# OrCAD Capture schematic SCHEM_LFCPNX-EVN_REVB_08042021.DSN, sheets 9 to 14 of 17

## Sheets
9 Bank-6 Extended Bank: size B; title: Bank-6 Extened Bank
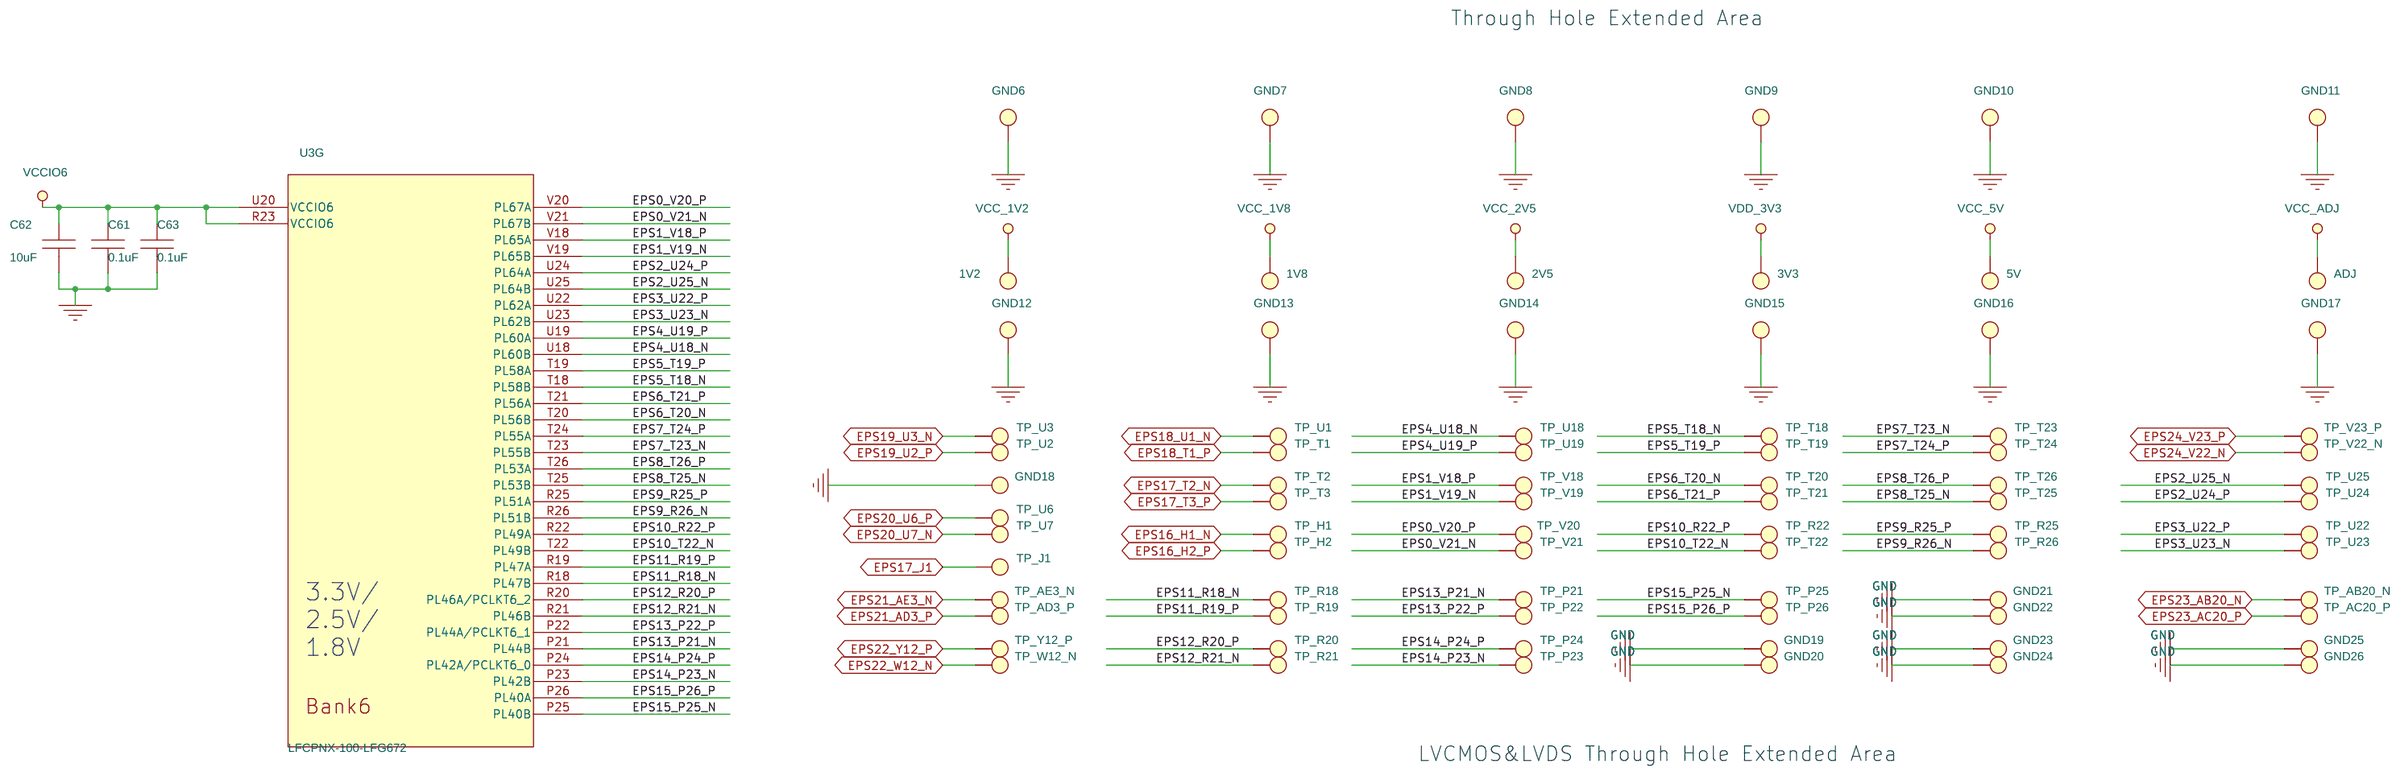
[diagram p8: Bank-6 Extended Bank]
10 Bank-7 Raspberry PI: size B; title: Bank-7 Raspberry PI
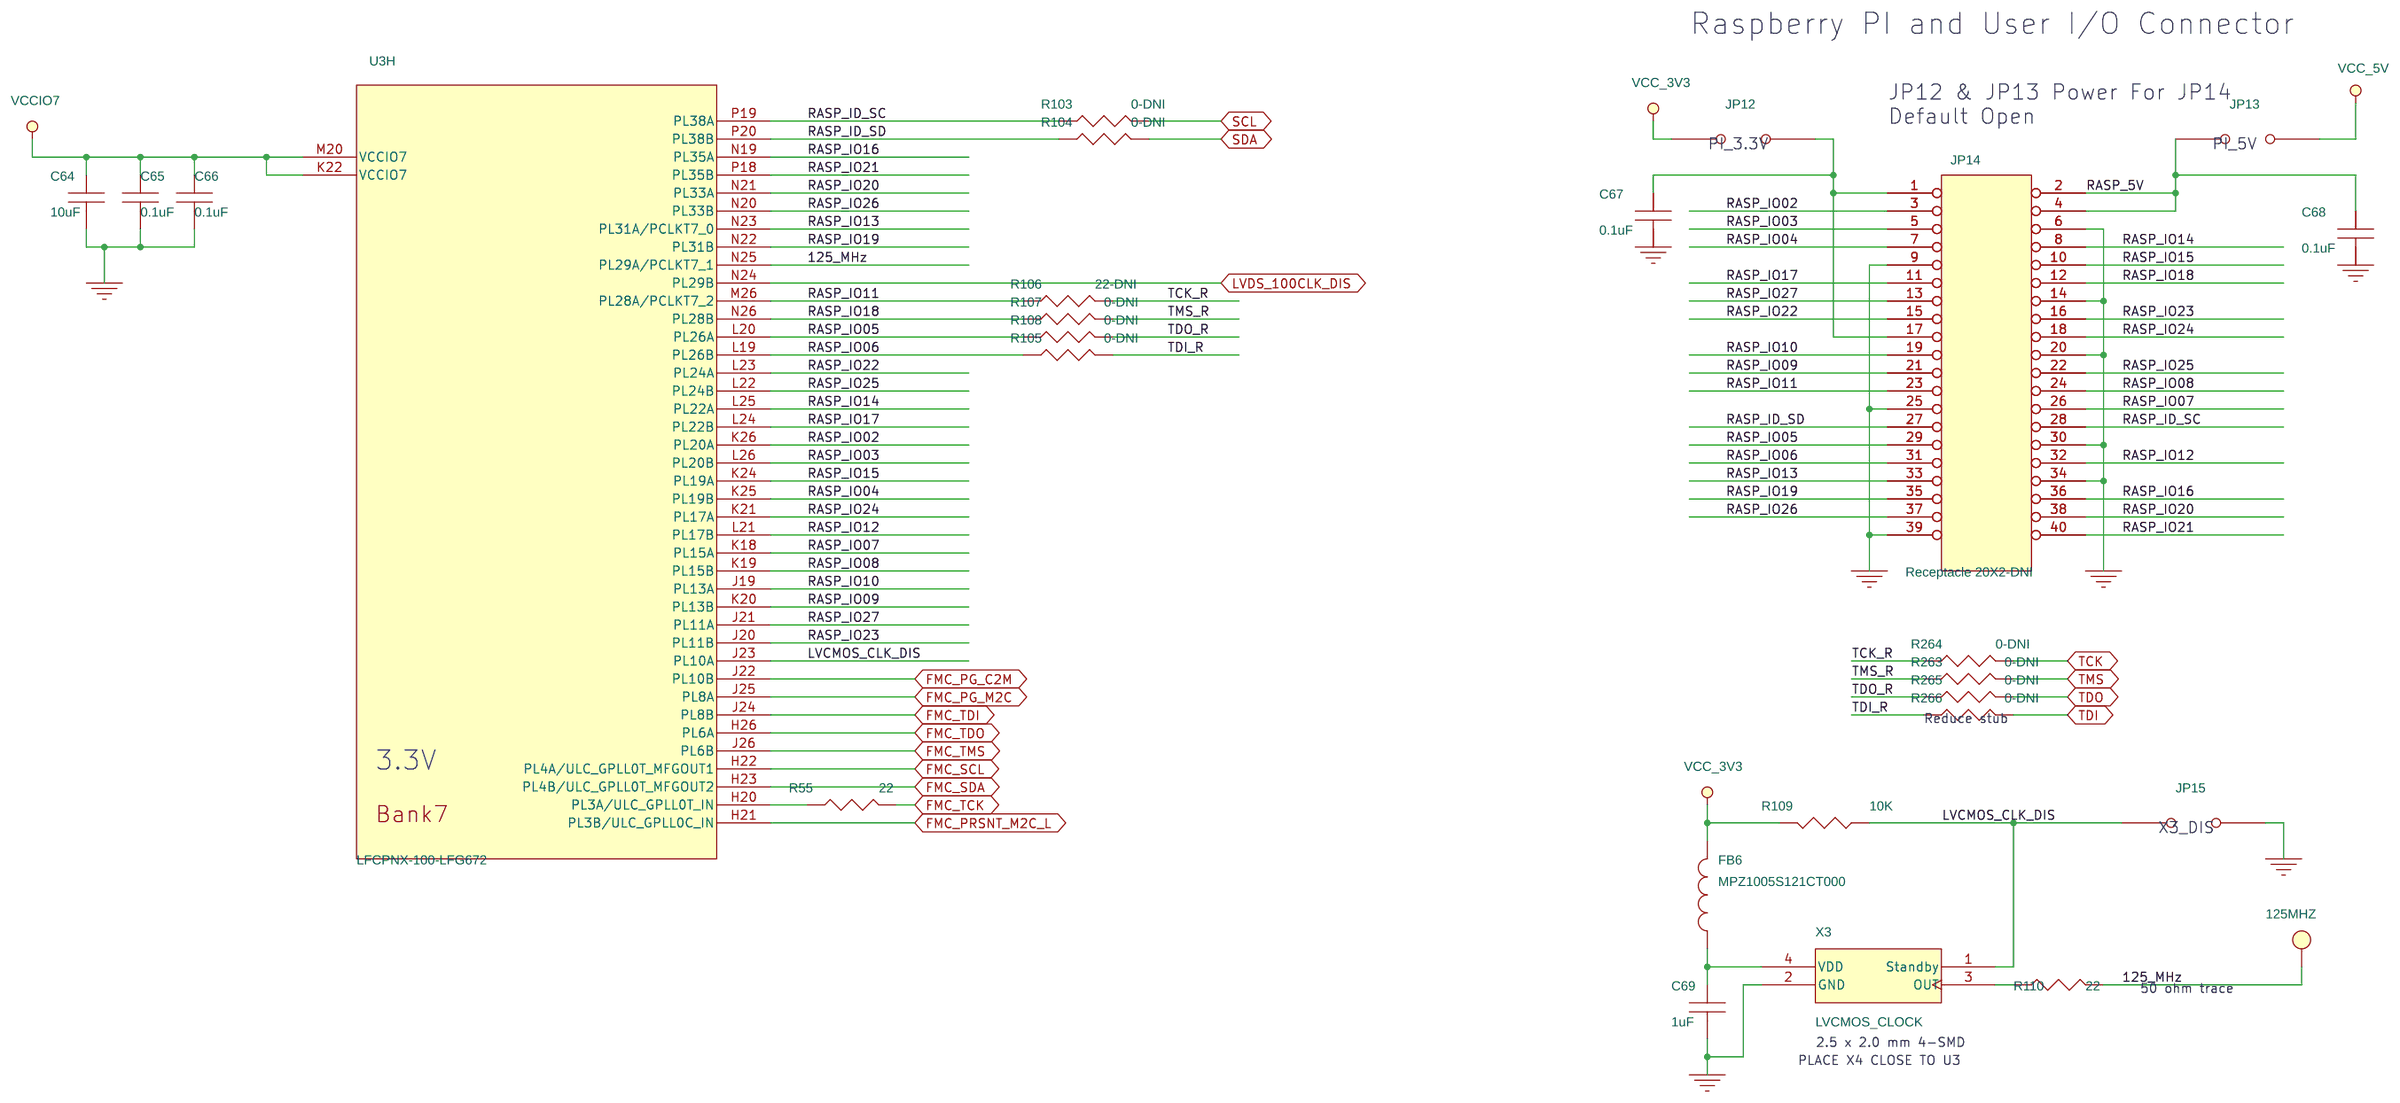
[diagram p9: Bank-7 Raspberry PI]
11 SerDes: size C; title: SerDes
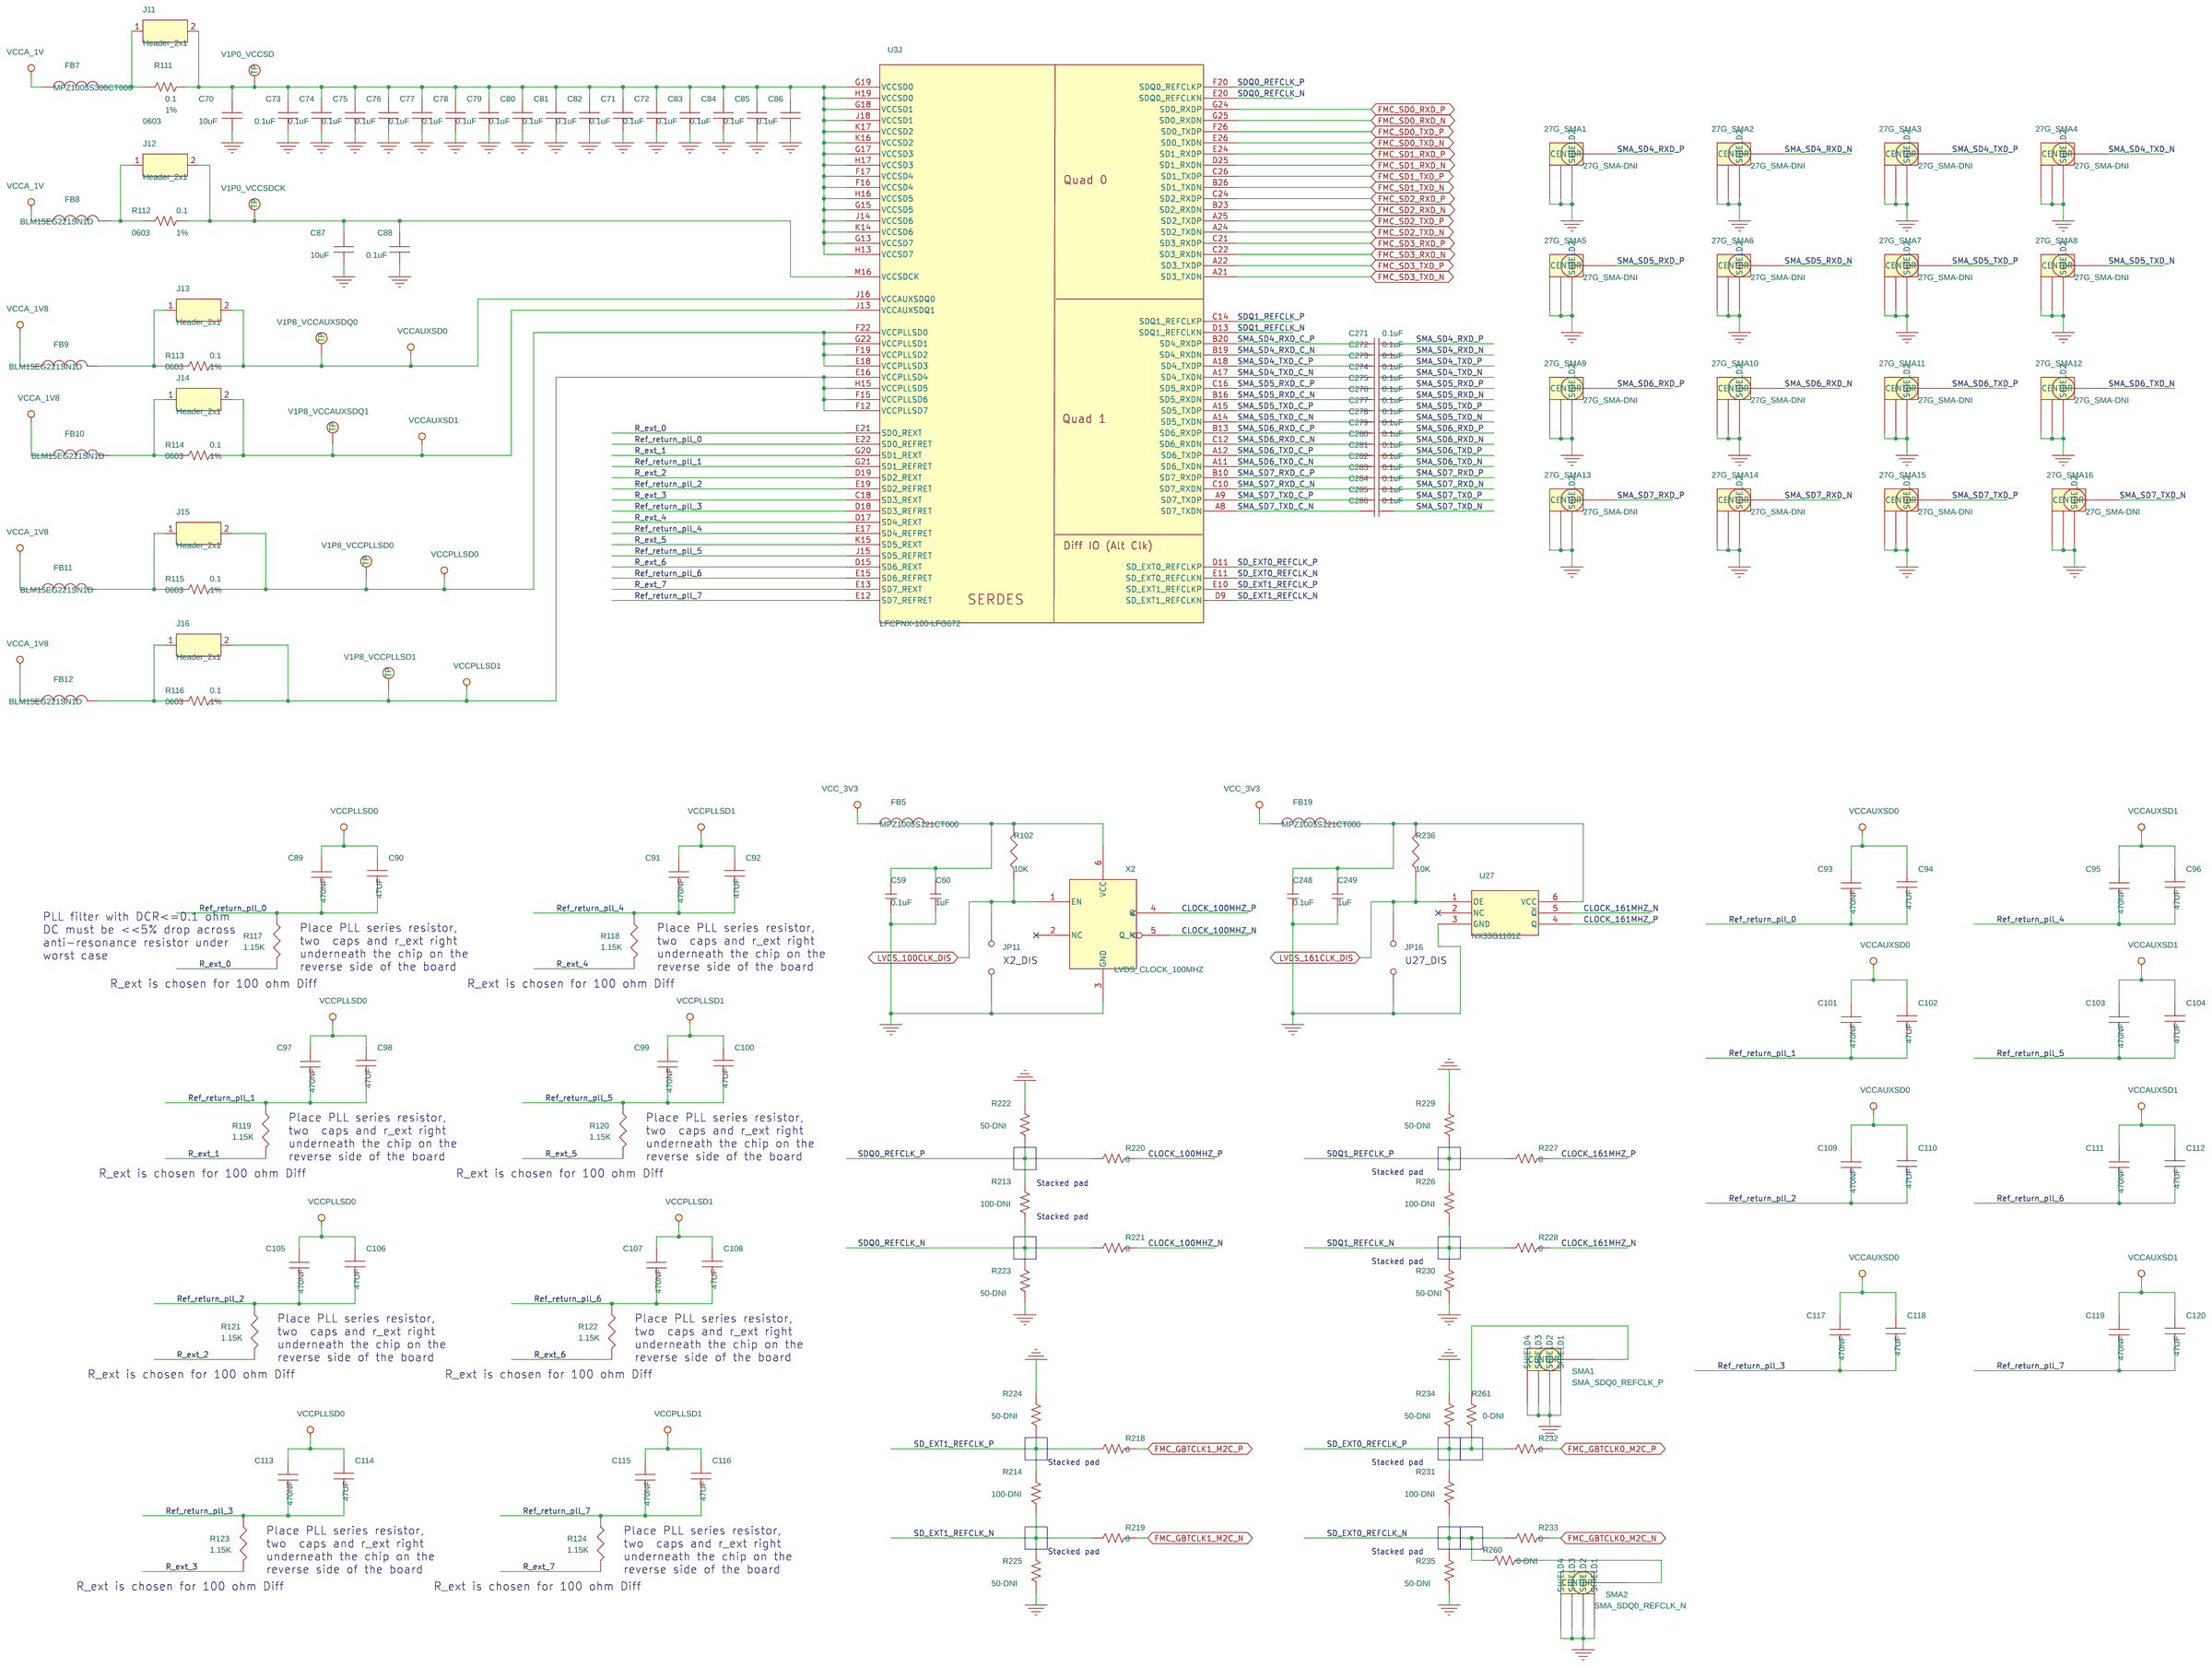
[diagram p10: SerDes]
12 ADC: size B; title: ADC
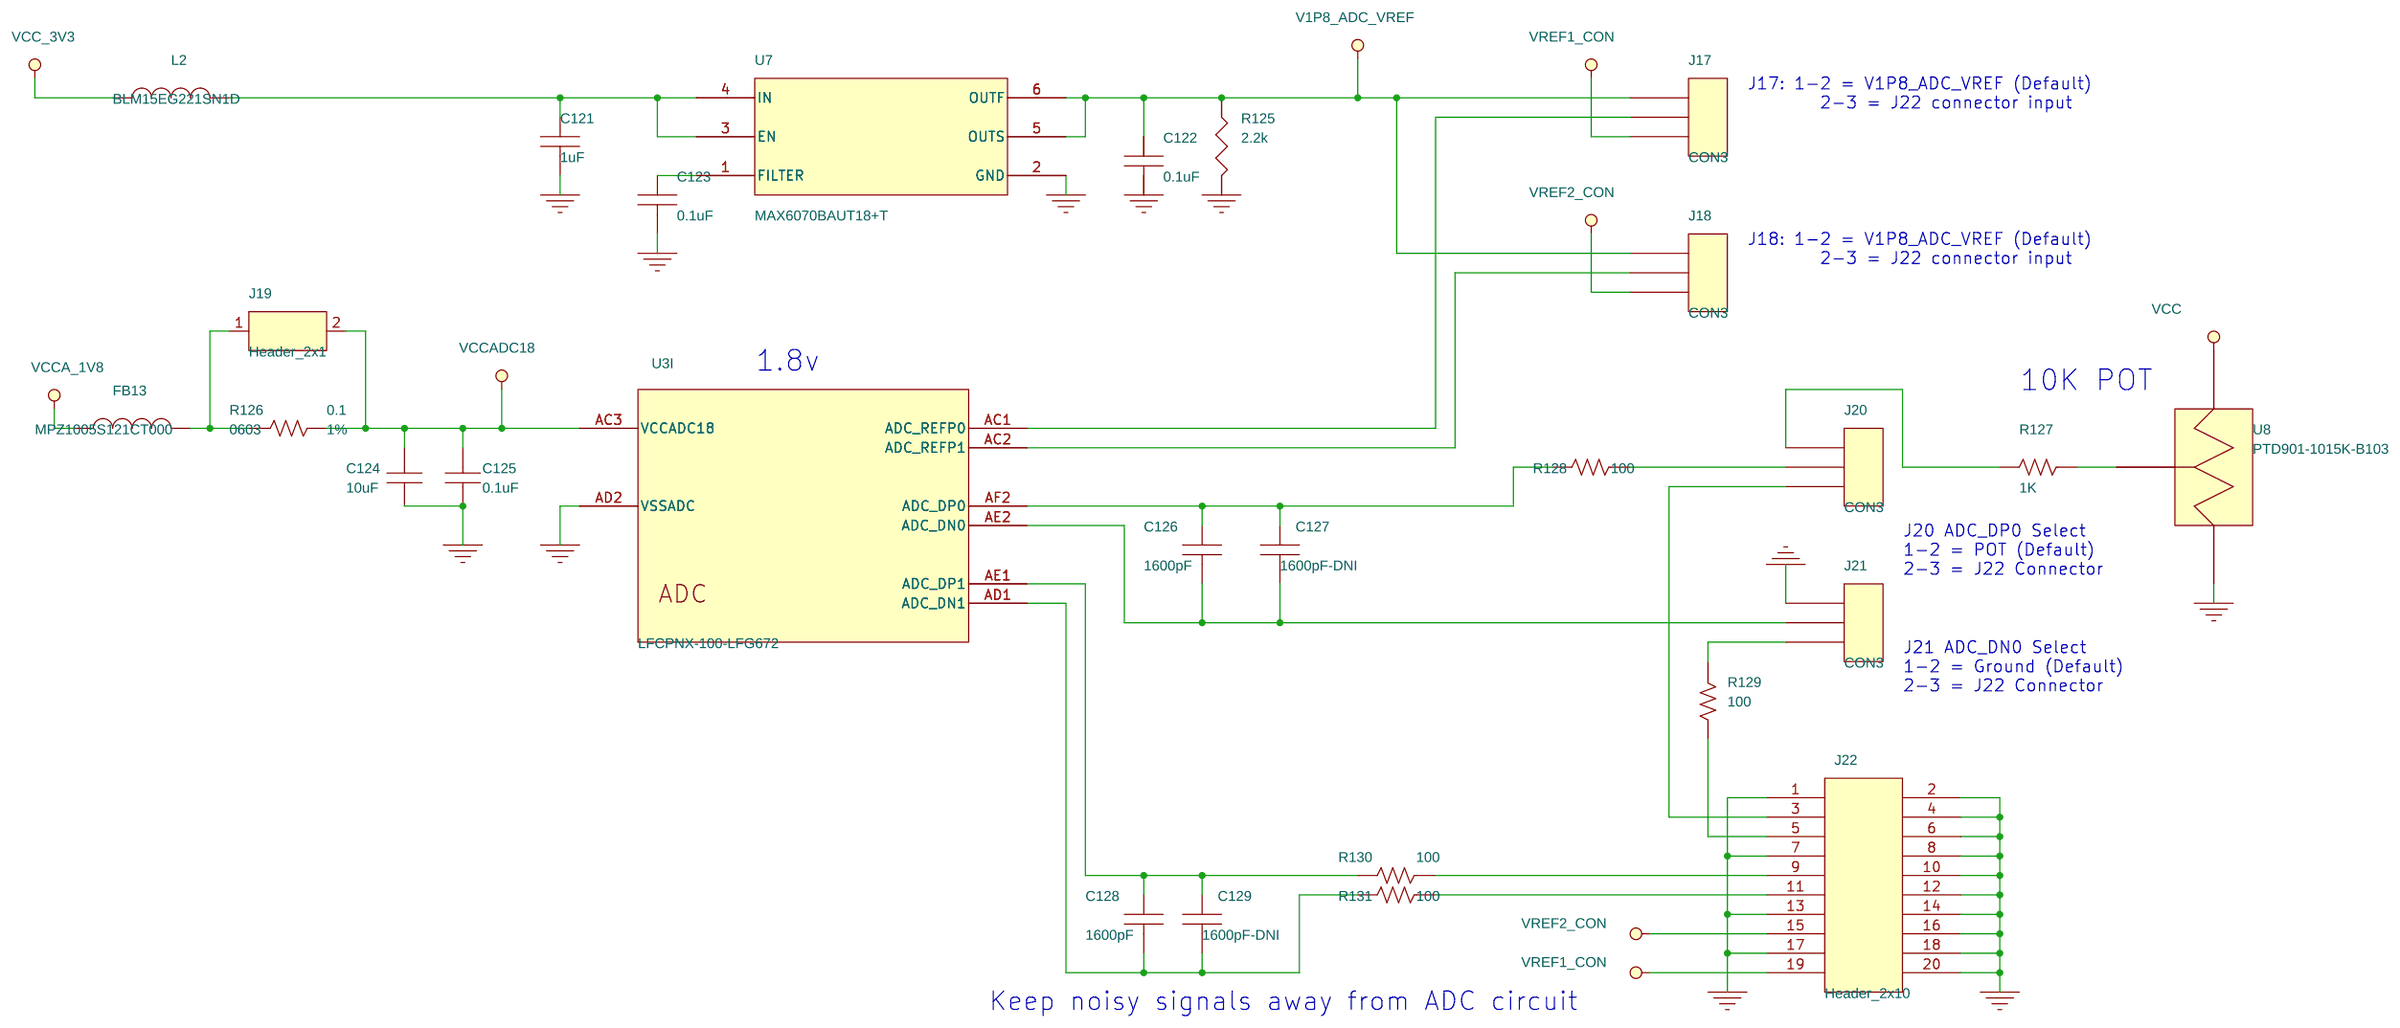
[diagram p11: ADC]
13 Bank Power: size B; title: Bank Power
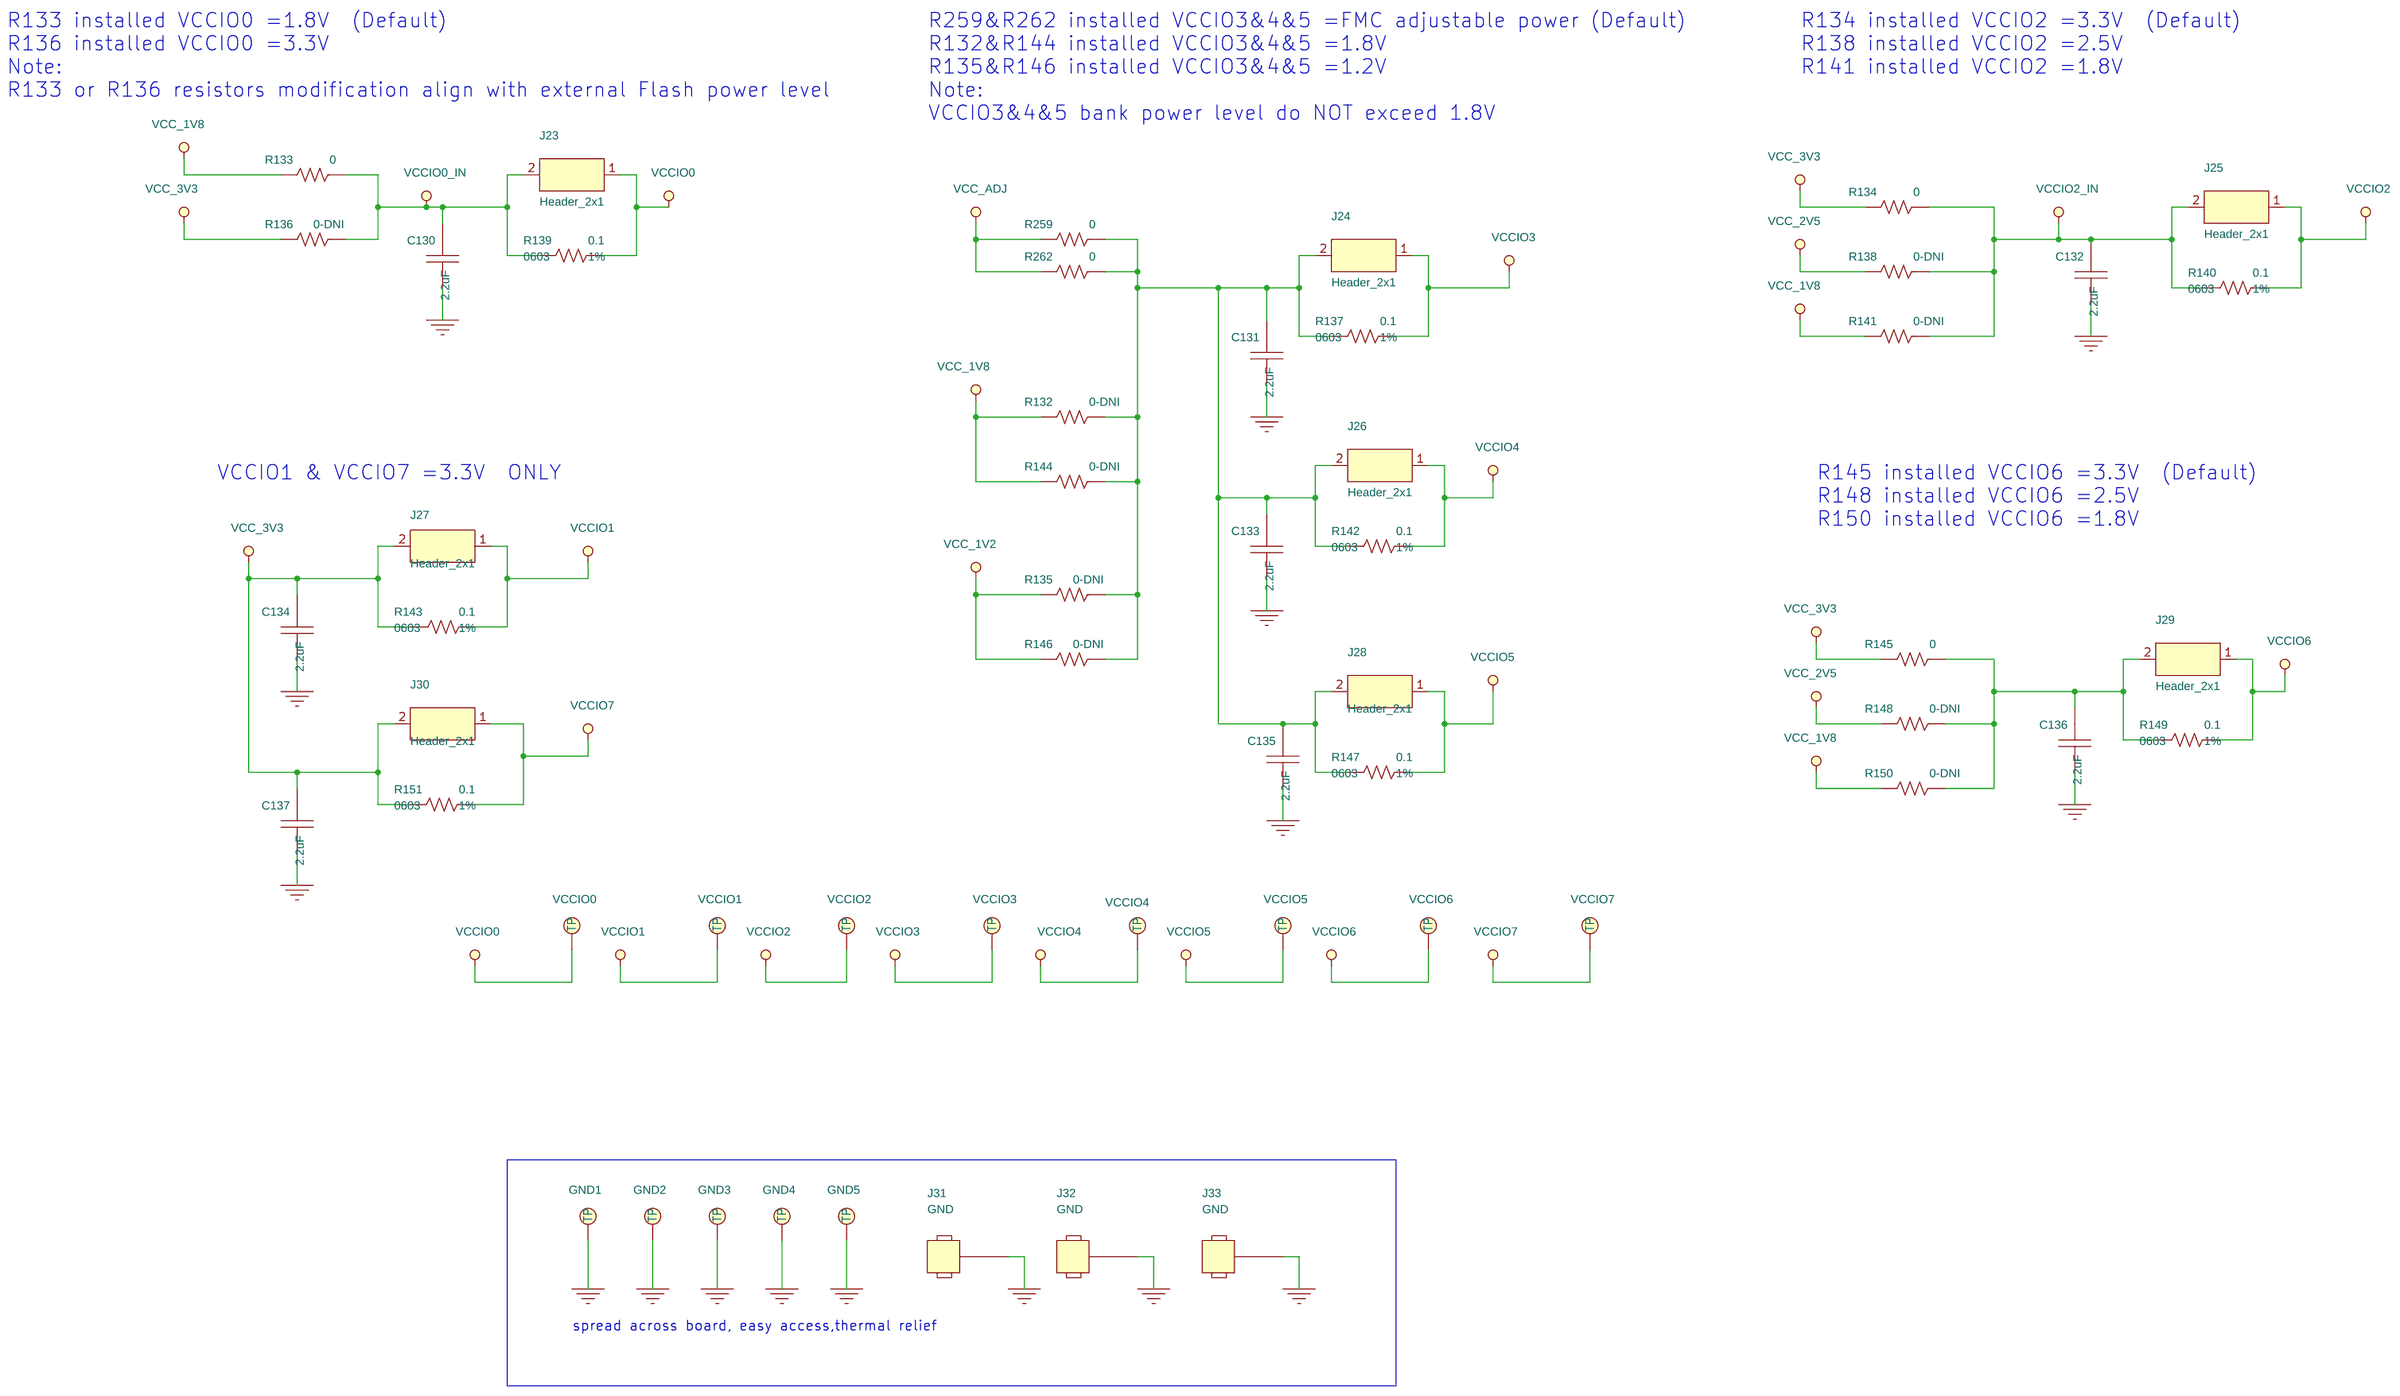
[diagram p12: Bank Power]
14 Power Decoupling: size B; title: Power Decoupling
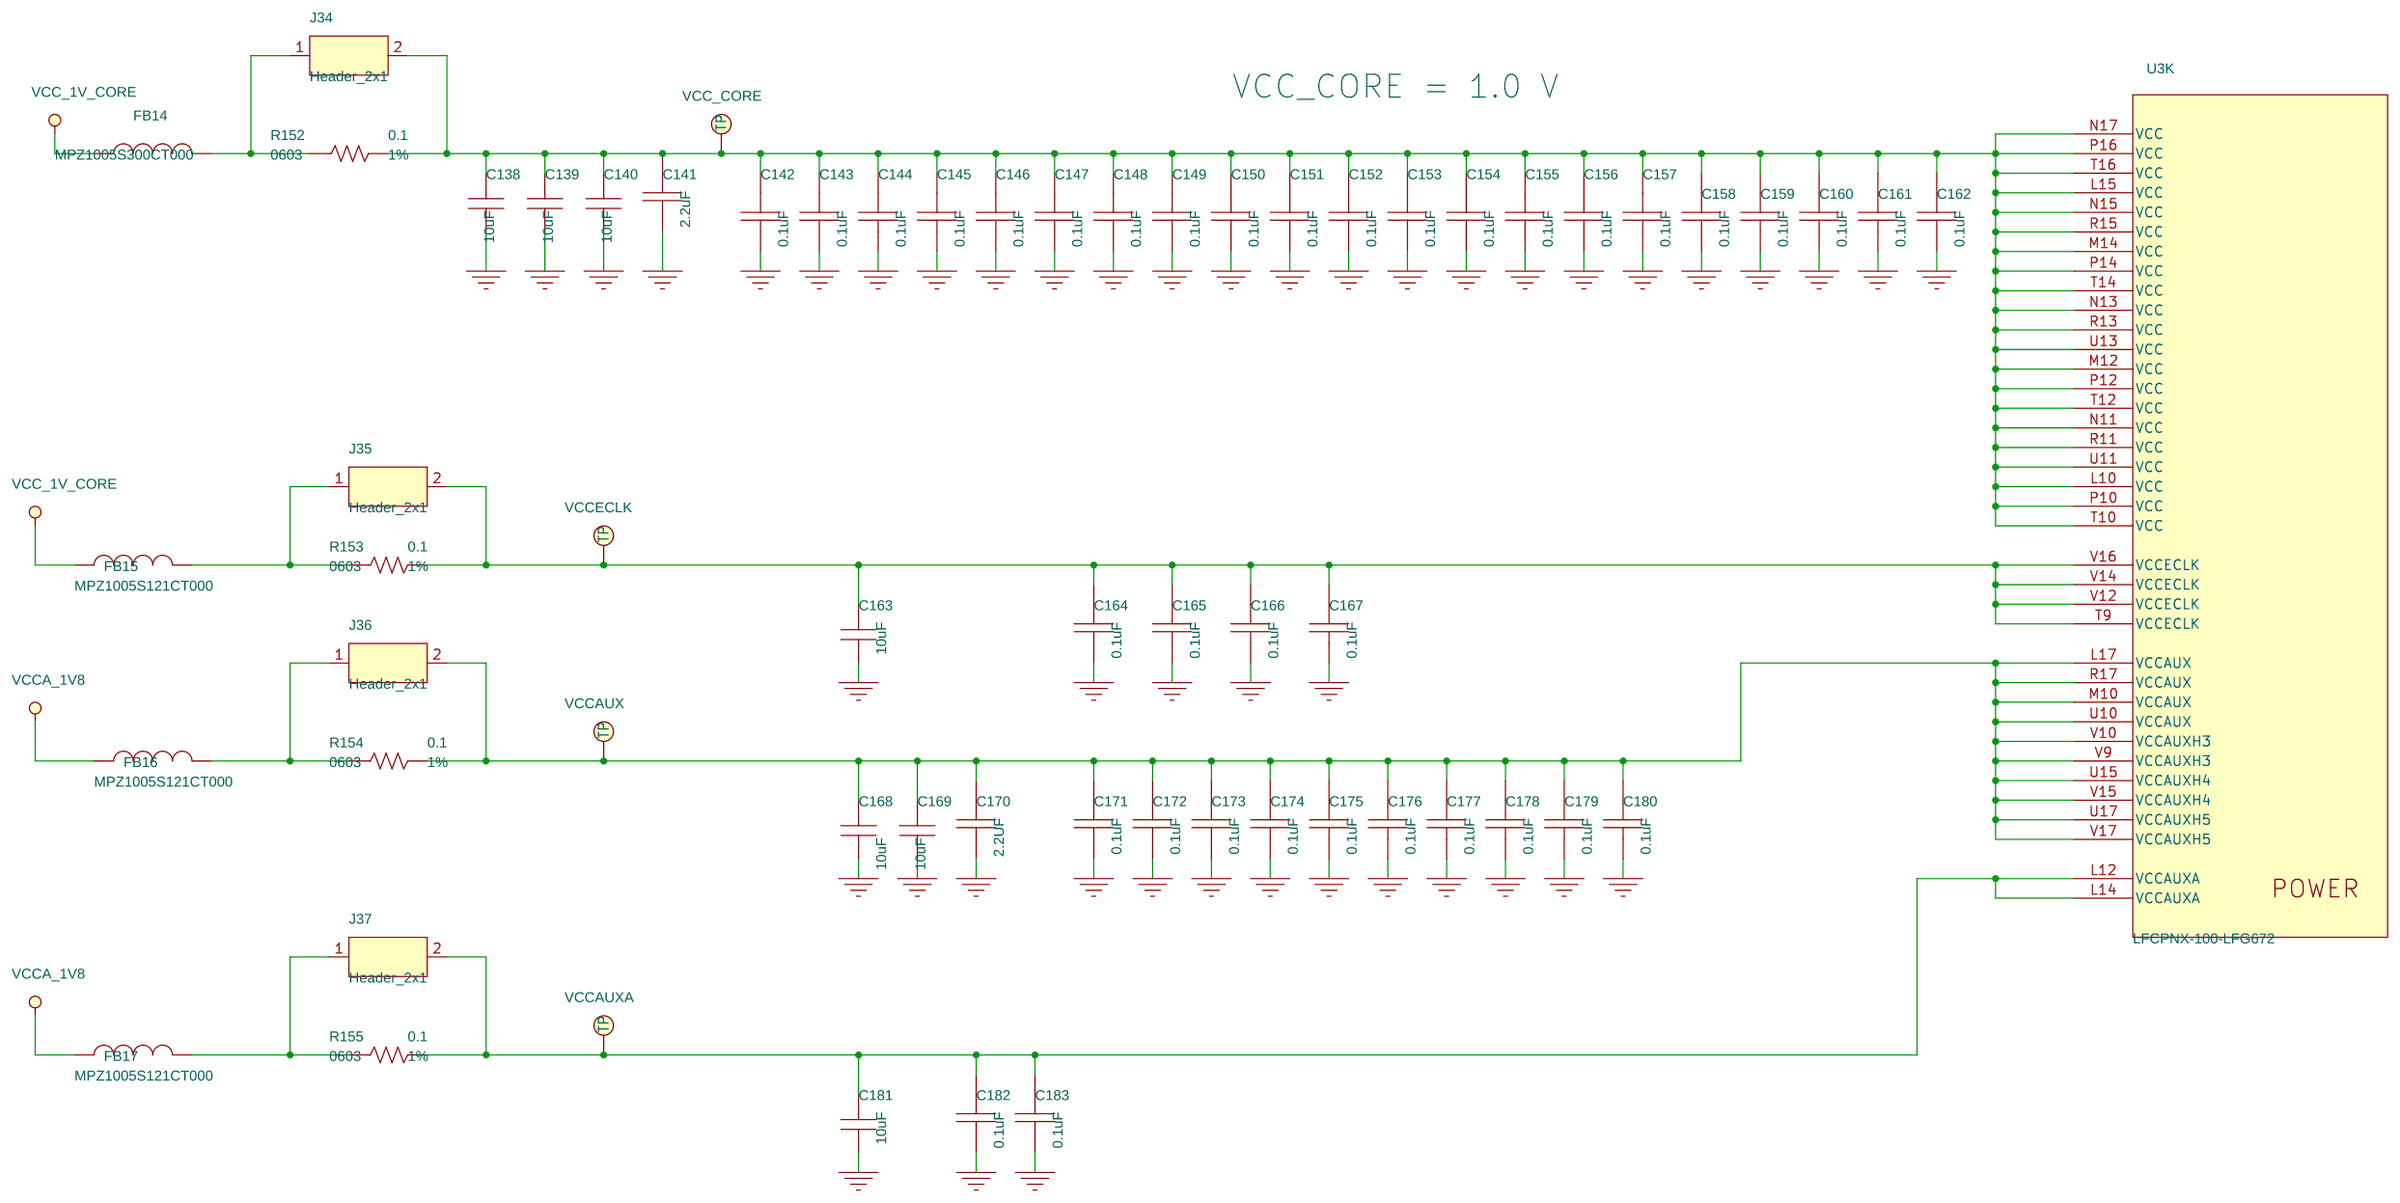
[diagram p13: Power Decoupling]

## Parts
sheet ADC
C121  1uF  [C0603]
C122  0.1uF  [C0201]
C123  0.1uF  [C0201]
C124  10uF  [C0402]
C125  0.1uF  [C0201]
C126  1600pF  [C0805]
C127  1600pF-DNI  [C0805]
C128  1600pF  [C0805]
C129  1600pF-DNI  [C0805]
FB13  MPZ1005S121CT000  [FB0402]
J17  CON3  [CON3]
J18  CON3  [CON3]
J19  Header_2x1  [Header_2x1]
J20  CON3  [CON3]
J21  CON3  [CON3]
J22  Header_2x10  [Header_2x10]
L2  BLM15EG221SN1D  [FB0402]
R125  2.2k  [R0603]
R126  0.1  [0603]
R127  1K  [R0805]
R128  100  [R0805]
R129  100  [R0805]
R130  100  [R0805]
R131  100  [R0805]
U7  MAX6070BAUT18+T  [SOT23-6_MAX6070]
U8  PTD901-1015K-B103  [PTD901_1015K_B103]
sheet Bank Power
C130  2.2uF  [RLP-133]
C131  2.2uF  [RLP-133]
C132  2.2uF  [RLP-133]
C133  2.2uF  [RLP-133]
C134  2.2uF  [RLP-133]
C135  2.2uF  [RLP-133]
C136  2.2uF  [RLP-133]
C137  2.2uF  [RLP-133]
GND1  TestPoint_Hole  [TP]
GND2  TestPoint_Hole  [TP]
GND3  TestPoint_Hole  [TP]
GND4  TestPoint_Hole  [TP]
GND5  TestPoint_Hole  [TP]
J23  Header_2x1  [Header_2x1]
J24  Header_2x1  [Header_2x1]
J25  Header_2x1  [Header_2x1]
J26  Header_2x1  [Header_2x1]
J27  Header_2x1  [Header_2x1]
J28  Header_2x1  [Header_2x1]
J29  Header_2x1  [Header_2x1]
J30  Header_2x1  [Header_2x1]
J31  GND  [TUR_TH]
J32  GND  [TUR_TH]
J33  GND  [TUR_TH]
R132  0-DNI  [R0603]
R133  0  [R0603]
R134  0  [R0603]
R135  0-DNI  [R0603]
R136  0-DNI  [R0603]
R137  0.1  [0603]
R138  0-DNI  [R0603]
R139  0.1  [0603]
R140  0.1  [0603]
R141  0-DNI  [R0603]
R142  0.1  [0603]
R143  0.1  [0603]
R144  0-DNI  [R0603]
R145  0  [R0603]
R146  0-DNI  [R0603]
R147  0.1  [0603]
R148  0-DNI  [R0603]
R149  0.1  [0603]
R150  0-DNI  [R0603]
R151  0.1  [0603]
R259  0  [R0603]
R262  0  [R0603]
VCCIO0  TP_S_40_63  [tp_s_40_63]
VCCIO1  TP_S_40_63  [tp_s_40_63]
VCCIO2  TP_S_40_63  [tp_s_40_63]
VCCIO3  TP_S_40_63  [tp_s_40_63]
VCCIO4  TP_S_40_63  [tp_s_40_63]
VCCIO5  TP_S_40_63  [tp_s_40_63]
VCCIO6  TP_S_40_63  [tp_s_40_63]
VCCIO7  TP_S_40_63  [tp_s_40_63]
sheet Bank-6 Extended Bank
1V2  T POINT R  [TP]
1V8  T POINT R  [TP]
2V5  T POINT R  [TP]
3V3  T POINT R  [TP]
5V  T POINT R  [TP]
ADJ  T POINT R  [TP]
C61  0.1uF  [C0201]
C62  10uF  [C0402]
C63  0.1uF  [C0201]
GND6  T POINT R  [TP]
GND7  T POINT R  [TP]
GND8  T POINT R  [TP]
GND9  T POINT R  [TP]
GND10  T POINT R  [TP]
GND11  T POINT R  [TP]
GND12  T POINT R  [TP]
GND13  T POINT R  [TP]
GND14  T POINT R  [TP]
GND15  T POINT R  [TP]
GND16  T POINT R  [TP]
GND17  T POINT R  [TP]
GND18  T POINT R  [TP]
GND19  T POINT R  [TP]
GND20  T POINT R  [TP]
GND21  T POINT R  [TP]
GND22  T POINT R  [TP]
GND23  T POINT R  [TP]
GND24  T POINT R  [TP]
GND25  T POINT R  [TP]
GND26  T POINT R  [TP]
TP_AB20_N  T POINT R  [TP]
TP_AC20_P  T POINT R  [TP]
TP_AD3_P  T POINT R  [TP]
TP_AE3_N  T POINT R  [TP]
TP_H1  T POINT R  [TP]
TP_H2  T POINT R  [TP]
TP_J1  T POINT R  [TP]
TP_P21  T POINT R  [TP]
TP_P22  T POINT R  [TP]
TP_P23  T POINT R  [TP]
TP_P24  T POINT R  [TP]
TP_P25  T POINT R  [TP]
TP_P26  T POINT R  [TP]
TP_R18  T POINT R  [TP]
TP_R19  T POINT R  [TP]
TP_R20  T POINT R  [TP]
TP_R21  T POINT R  [TP]
TP_R22  T POINT R  [TP]
TP_R25  T POINT R  [TP]
TP_R26  T POINT R  [TP]
TP_T1  T POINT R  [TP]
TP_T2  T POINT R  [TP]
TP_T3  T POINT R  [TP]
TP_T18  T POINT R  [TP]
TP_T19  T POINT R  [TP]
TP_T20  T POINT R  [TP]
TP_T21  T POINT R  [TP]
TP_T22  T POINT R  [TP]
TP_T23  T POINT R  [TP]
TP_T24  T POINT R  [TP]
TP_T25  T POINT R  [TP]
TP_T26  T POINT R  [TP]
TP_U1  T POINT R  [TP]
TP_U2  T POINT R  [TP]
TP_U3  T POINT R  [TP]
TP_U6  T POINT R  [TP]
TP_U7  T POINT R  [TP]
TP_U18  T POINT R  [TP]
TP_U19  T POINT R  [TP]
TP_U22  T POINT R  [TP]
TP_U23  T POINT R  [TP]
TP_U24  T POINT R  [TP]
TP_U25  T POINT R  [TP]
TP_V18  T POINT R  [TP]
TP_V19  T POINT R  [TP]
TP_V20  T POINT R  [TP]
TP_V21  T POINT R  [TP]
TP_V22_N  T POINT R  [TP]
TP_V23_P  T POINT R  [TP]
TP_W12_N  T POINT R  [TP]
TP_Y12_P  T POINT R  [TP]
sheet Bank-7 Raspberry PI
125MHZ  TestPoint_SMT  [TPC32]
C64  10uF  [C0402]
C65  0.1uF  [C0201]
C66  0.1uF  [C0201]
C67  0.1uF  [C0201]
C68  0.1uF  [C0201]
C69  1uF  [C0603]
FB6  MPZ1005S121CT000  [FB0402]
JP12  JUMPER-DNI  [Header_1x2]
JP13  JUMPER-DNI  [Header_1x2]
JP14  Receptacle 20X2-DNI  [HDR254-2X20_socket]
JP15  JUMPER  [Header_1x2]
R55  22  [R0402]
R103  0-DNI  [R0603]
R104  0-DNI  [R0603]
R105  0-DNI  [R0402]
R106  22-DNI  [R0402]
R107  0-DNI  [R0402]
R108  0-DNI  [R0402]
R109  10K  [R0603]
R110  22  [R0402]
R263  0-DNI  [R0402]
R264  0-DNI  [R0402]
R265  0-DNI  [R0402]
R266  0-DNI  [R0402]
U3  LFCPNX-100-LFG672  [BGA672-1P0]  (sections A,B,C,D,E,F,G,H,I,J,K,L,M,N)
X3  LVCMOS_CLOCK  [ASFLMB_125_000MHZ-LR-T]
sheet Power Decoupling
C138  10uF  [C0402]
C139  10uF  [C0402]
C140  10uF  [C0402]
C141  2.2uF  [RLP-133]
C142  0.1uF  [C0201]
C143  0.1uF  [C0201]
C144  0.1uF  [C0201]
C145  0.1uF  [C0201]
C146  0.1uF  [C0201]
C147  0.1uF  [C0201]
C148  0.1uF  [C0201]
C149  0.1uF  [C0201]
C150  0.1uF  [C0201]
C151  0.1uF  [C0201]
C152  0.1uF  [C0201]
C153  0.1uF  [C0201]
C154  0.1uF  [C0201]
C155  0.1uF  [C0201]
C156  0.1uF  [C0201]
C157  0.1uF  [C0201]
C158  0.1uF  [C0201]
C159  0.1uF  [C0201]
C160  0.1uF  [C0201]
C161  0.1uF  [C0201]
C162  0.1uF  [C0201]
C163  10uF  [C0402]
C164  0.1uF  [C0201]
C165  0.1uF  [C0201]
C166  0.1uF  [C0201]
C167  0.1uF  [C0201]
C168  10uF  [C0402]
C169  10uF  [C0402]
C170  2.2UF  [RLP-133]
C171  0.1uF  [C0201]
C172  0.1uF  [C0201]
C173  0.1uF  [C0201]
C174  0.1uF  [C0201]
C175  0.1uF  [C0201]
C176  0.1uF  [C0201]
C177  0.1uF  [C0201]
C178  0.1uF  [C0201]
C179  0.1uF  [C0201]
C180  0.1uF  [C0201]
C181  10uF  [C0402]
C182  0.1uF  [C0201]
C183  0.1uF  [C0201]
FB14  MPZ1005S300CT000  [FB0402]
FB15  MPZ1005S121CT000  [FB0402]
FB16  MPZ1005S121CT000  [FB0402]
FB17  MPZ1005S121CT000  [FB0402]
J34  Header_2x1  [Header_2x1]
J35  Header_2x1  [Header_2x1]
J36  Header_2x1  [Header_2x1]
J37  Header_2x1  [Header_2x1]
R152  0.1  [0603]
R153  0.1  [0603]
R154  0.1  [0603]
R155  0.1  [0603]
VCC_CORE  TP_S_40_63  [tp_s_40_63]
VCCAUX  TP_S_40_63  [tp_s_40_63]
VCCAUXA  TP_S_40_63  [tp_s_40_63]
VCCECLK  TP_S_40_63  [tp_s_40_63]
sheet SerDes
27G_SMA1  27G_SMA-DNI  [SV_SF2921-61356-2S]
27G_SMA2  27G_SMA-DNI  [SV_SF2921-61356-2S]
27G_SMA3  27G_SMA-DNI  [SV_SF2921-61345-2S]
27G_SMA4  27G_SMA-DNI  [SV_SF2921-61345-2S]
27G_SMA5  27G_SMA-DNI  [SV_SF2921-61356-2S]
27G_SMA6  27G_SMA-DNI  [SV_SF2921-61356-2S]
27G_SMA7  27G_SMA-DNI  [SV_SF2921-61345-2S]
27G_SMA8  27G_SMA-DNI  [SV_SF2921-61345-2S]
27G_SMA9  27G_SMA-DNI  [SV_SF2921-61356-2S]
27G_SMA10  27G_SMA-DNI  [SV_SF2921-61356-2S]
27G_SMA11  27G_SMA-DNI  [SV_SF2921-61345-2S]
27G_SMA12  27G_SMA-DNI  [SV_SF2921-61345-2S]
27G_SMA13  27G_SMA-DNI  [SV_SF2921-61356-2S]
27G_SMA14  27G_SMA-DNI  [SV_SF2921-61356-2S]
27G_SMA15  27G_SMA-DNI  [SV_SF2921-61345-2S]
27G_SMA16  27G_SMA-DNI  [SV_SF2921-61345-2S]
C59  0.1uF  [C0201]
C60  1uF  [C0603]
C70  10uF  [C0402]
C71  0.1uF  [C0201]
C72  0.1uF  [C0201]
C73  0.1uF  [C0201]
C74  0.1uF  [C0201]
C75  0.1uF  [C0201]
C76  0.1uF  [C0201]
C77  0.1uF  [C0201]
C78  0.1uF  [C0201]
C79  0.1uF  [C0201]
C80  0.1uF  [C0201]
C81  0.1uF  [C0201]
C82  0.1uF  [C0201]
C83  0.1uF  [C0201]
C84  0.1uF  [C0201]
C85  0.1uF  [C0201]
C86  0.1uF  [C0201]
C87  10uF  [C0402]
C88  0.1uF  [C0201]
C89  470NF  [C0402]
C90  47UF  [C0603]
C91  470NF  [C0402]
C92  47UF  [C0603]
C93  470NF  [C0402]
C94  47UF  [C0603]
C95  470NF  [C0402]
C96  47UF  [C0603]
C97  470NF  [C0402]
C98  47UF  [C0603]
C99  470NF  [C0402]
C100  47UF  [C0603]
C101  470NF  [C0402]
C102  47UF  [C0603]
C103  470NF  [C0402]
C104  47UF  [C0603]
C105  470NF  [C0402]
C106  47UF  [C0603]
C107  470NF  [C0402]
C108  47UF  [C0603]
C109  470NF  [C0402]
C110  47UF  [C0603]
C111  470NF  [C0402]
C112  47UF  [C0603]
C113  470NF  [C0402]
C114  47UF  [C0603]
C115  470NF  [C0402]
C116  47UF  [C0603]
C117  470NF  [C0402]
C118  47UF  [C0603]
C119  470NF  [C0402]
C120  47UF  [C0603]
C248  0.1uF  [C0201]
C249  1uF  [C0603]
C271  0.1uF  [C0402]
C272  0.1uF  [C0402]
C273  0.1uF  [C0402]
C274  0.1uF  [C0402]
C275  0.1uF  [C0402]
C276  0.1uF  [C0402]
C277  0.1uF  [C0402]
C278  0.1uF  [C0402]
C279  0.1uF  [C0402]
C280  0.1uF  [C0402]
C281  0.1uF  [C0402]
C282  0.1uF  [C0402]
C283  0.1uF  [C0402]
C284  0.1uF  [C0402]
C285  0.1uF  [C0402]
C286  0.1uF  [C0402]
FB5  MPZ1005S121CT000  [FB0402]
FB7  MPZ1005S300CT000  [FB0402]
FB8  BLM15EG221SN1D  [FB0402]
FB9  BLM15EG221SN1D  [FB0402]
FB10  BLM15EG221SN1D  [FB0402]
FB11  BLM15EG221SN1D  [FB0402]
FB12  BLM15EG221SN1D  [FB0402]
FB19  MPZ1005S121CT000  [FB0402]
J11  Header_2x1  [Header_2x1]
J12  Header_2x1  [Header_2x1]
J13  Header_2x1  [Header_2x1]
J14  Header_2x1  [Header_2x1]
J15  Header_2x1  [Header_2x1]
J16  Header_2x1  [Header_2x1]
JP11  JUMPER  [Header_1x2]
JP16  JUMPER  [Header_1x2]
R102  10K  [R0603]
R111  0.1  [0603]
R112  0.1  [0603]
R113  0.1  [0603]
R114  0.1  [0603]
R115  0.1  [0603]
R116  0.1  [0603]
R117  1.15K  [R0402]
R118  1.15K  [R0402]
R119  1.15K  [R0402]
R120  1.15K  [R0402]
R121  1.15K  [R0402]
R122  1.15K  [R0402]
R123  1.15K  [R0402]
R124  1.15K  [R0402]
R213  100-DNI  [R0402]
R214  100-DNI  [R0402]
R218  0  [R0402]
R219  0  [R0402]
R220  0  [R0402]
R221  0  [R0402]
R222  50-DNI  [R0402]
R223  50-DNI  [R0402]
R224  50-DNI  [R0402]
R225  50-DNI  [R0402]
R226  100-DNI  [R0402]
R227  0  [R0402]
R228  0  [R0402]
R229  50-DNI  [R0402]
R230  50-DNI  [R0402]
R231  100-DNI  [R0402]
R232  0  [R0402]
R233  0  [R0402]
R234  50-DNI  [R0402]
R235  50-DNI  [R0402]
R236  10K  [R0603]
R260  0-DNI  [R0402]
R261  0-DNI  [R0402]
SMA1  SMA_SDQ0_REFCLK_P  [CONN_SMA-J-P-H-ST-TH1]
SMA2  SMA_SDQ0_REFCLK_N  [CONN_SMA-J-P-H-ST-TH1]
U27  NX33G1101Z  [NX32X25]
V1P0_VCCSD  TP_S_40_63  [tp_s_40_63]
V1P0_VCCSDCK  TP_S_40_63  [tp_s_40_63]
V1P8_VCCAUXSDQ0  TP_S_40_63  [tp_s_40_63]
V1P8_VCCAUXSDQ1  TP_S_40_63  [tp_s_40_63]
V1P8_VCCPLLSD0  TP_S_40_63  [tp_s_40_63]
V1P8_VCCPLLSD1  TP_S_40_63  [tp_s_40_63]
X2  LVDS_CLOCK_100MHZ  [ASTMUPLDE-100p000MHZ-LJ-E-T]

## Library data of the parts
C61 C63 C65-C68 C121-C123 = 0u1_0402: CAP CER 0.1UF 25V 10% X5R 0201; Manufacturer: Murata; Manufacturer Part Number: GRM033R61E104KE14J
C70 C87 C124 = CAP_CER_100nF_0402_10V: CAP CER 0.1UF 10V X7R 0402; MFG: Wurth; MFG P/N: 885012205018; Manufacturer: Wurth; Manufacturer Part Number: 885012205018
C71-C86 C88 C125 = CAP_CER_100nF_0402_10V: CAP CER 0.1UF 25V 10% X5R 0201; Manufacturer: Murata; Manufacturer Part Number: GRM033R61E104KE14J
C126 C128 = 0u1_0402: CAP CER 1.6nF 50V 5% X5R 0201; Digikey P/N: 399-15458-1-ND; Manufacturer: Kemet; Manufacturer Part Number: C0805C162J5GAC7800
C127 C129 = 0u1_0402: CAP CER 1.6nF 50V 5% X5R 0201; Assy: DNI; Digikey P/N: 399-15458-1-ND; Manufacturer: Kemet; Manufacturer Part Number: C0805C162J5GAC7800
FB5 FB6 FB13 FB19 = INDUCTOR_1: FERRITE BEAD 120 OHM 0402 1LN; Manufacturer: TDK Corporation
J17 J18 J20 J21 = CON3: 3 Positions Header, Unshrouded Connector 0.100" (2.54mm) Through Hole Gold; Manufacturer: Wurth; Manufacturer Part Number: 61300311121; PART_NUMBER: 61300311121
J11-J16 J19 J23-J30 J34-J37 = Header_2x1
J22 = Header_2x10
L2 = FB0603: FERRITE CHIP 600 OHM 500MA 0603
R125 = RES_1K_1W16_0402_5P: RES SMD 1K OHM 1% 1/10W 0402; Manufacturer: Panasonic; Manufacturer Part Number: ERJ-2RKF1001X
R111-R116 R126 R132 R135-R144 R146-R155 = R_v3: COMPFIXED: NO; COMPGROUP: 0; COMPHEIGHT: 0.000; COMPKEY: NO; COMPLOC: [970.000,1160.000]; COMPLOCKED: NO; COMPROT: 180; COMPSIDE: TOP; DECOUPLER: NO; FPLIST: AX/RC05,SM/R_0603; MEMORY: NO; Tollerance: 1%
R127-R131 = R_v3: RES 1K OHM 1/10W 1% 0603 SMD; COMPFIXED: NO; COMPGROUP: 0; COMPHEIGHT: 0.000; COMPKEY: NO; COMPLOC: [2340.000,1470.000]; COMPLOCKED: NO; COMPROT: 0; COMPSIDE: BOT; DECOUPLER: NO; MEMORY: NO; Populate: DI
U7 = MAX6070BAUT18+T_0
U8 = PTD901-1015K-B103-ND
C130-C137 C141 C170 = CAP_SMT_0805: CAP CER 2.2UF 16V X7R 0805; MAX_TEMP: 125; MFG: Samsung Electro-Mechanics; MFG P/N: CL21B225KOFNNNE; Manufacturer: Samsung Electro-Mechanics; Manufacturer Part Number: CL21B225KOFNNNE; VENDOR: Digikey; VENDOR P/N: 1276-1162-1-ND
GND1-GND5 V1P0_VCCSD V1P0_VCCSDCK V1P8_VCCAUXSDQ0 V1P8_VCCAUXSDQ1 V1P8_VCCPLLSD0 V1P8_VCCPLLSD1 VCC_CORE VCCAUX VCCAUXA VCCECLK VCCIO0-VCCIO7 = TP_S_40_63: Assy: DNI
J31-J33 = HEADER_1: BOM1_Sensor_Population: POPULATE; BOM2_DUT_Population: DNP; Man. Part #: 1573-2; Manufacturer: Keystone Electronics
R133 R134 R145 R259 R262 = R_v3: COMPFIXED: NO; COMPHEIGHT: 0.000; COMPKEY: NO; COMPLOC: [970.000,1160.000]; COMPLOCKED: NO; COMPROT: 180; COMPSIDE: TOP; DECOUPLER: NO; FPLIST: AX/RC05,SM/R_0603; MEMORY: NO; Tollerance: 1%
1V2 = T_POINT_R_0: Assy: DNI; COMPFIXED: NO; COMPGROUP: 0; COMPHEIGHT: 0.000; COMPKEY: NO; COMPLOC: [300.000,3800.000]; COMPLOCKED: NO; COMPROT: 0; COMPSIDE: TOP; DECOUPLER: NO; MEMORY: NO
1V8 = T_POINT_R_0: Assy: DNI; COMPFIXED: NO; COMPGROUP: 0; COMPHEIGHT: 0.000; COMPKEY: NO; COMPLOC: [400.000,3800.000]; COMPLOCKED: NO; COMPROT: 0; COMPSIDE: TOP; DECOUPLER: NO; MEMORY: NO
2V5 TP_J1 TP_T18 TP_T22 = T_POINT_R_0: Assy: DNI; COMPFIXED: NO; COMPGROUP: 0; COMPHEIGHT: 0.000; COMPKEY: NO; COMPLOC: [500.000,3800.000]; COMPLOCKED: NO; COMPROT: 0; COMPSIDE: TOP; DECOUPLER: NO; MEMORY: NO
3V3 TP_V21 = T_POINT_R_0: Assy: DNI; COMPFIXED: NO; COMPGROUP: 0; COMPHEIGHT: 0.000; COMPKEY: NO; COMPLOC: [600.000,3800.000]; COMPLOCKED: NO; COMPROT: 0; COMPSIDE: TOP; DECOUPLER: NO; MEMORY: NO
5V ADJ = T_POINT_R_0: Assy: DNI; COMPFIXED: NO; COMPGROUP: 0; COMPHEIGHT: 0.000; COMPKEY: NO; COMPLOC: [700.000,3800.000]; COMPLOCKED: NO; COMPROT: 0; COMPSIDE: TOP; DECOUPLER: NO; MEMORY: NO
C62 = 0u1_0402: CAP CECAP CER 10UF 10V X5R 20% 0603; Manufacturer: Taiyo Yuden; Manufacturer Part Number: LMK107BJ106MALTD
GND6 = T_POINT_R_0: Assy: DNI; COMPFIXED: NO; COMPGROUP: 0; COMPHEIGHT: 0.000; COMPKEY: NO; COMPLOC: [200.000,3800.000]; COMPLOCKED: NO; COMPROT: 0; COMPSIDE: TOP; DECOUPLER: NO; MEMORY: NO
GND7-GND11 = T_POINT_R_0: Assy: DNI; COMPFIXED: NO; COMPGROUP: 0; COMPHEIGHT: 0.000; COMPKEY: NO; COMPLOC: [100.000,3800.000]; COMPLOCKED: NO; COMPROT: 0; COMPSIDE: TOP; DECOUPLER: NO; MEMORY: NO
GND12 GND15-GND26 TP_V23_P = T_POINT_R_0: Assy: DNI; COMPFIXED: NO; COMPGROUP: 0; COMPHEIGHT: 0.000; COMPKEY: NO; COMPLOC: [300.000,3000.000]; COMPLOCKED: NO; COMPROT: 0; COMPSIDE: TOP; DECOUPLER: NO; MEMORY: NO
GND13 TP_AE3_N = T_POINT_R_0: Assy: DNI; COMPFIXED: NO; COMPGROUP: 0; COMPHEIGHT: 0.000; COMPKEY: NO; COMPLOC: [300.000,3100.000]; COMPLOCKED: NO; COMPROT: 0; COMPSIDE: TOP; DECOUPLER: NO; MEMORY: NO
GND14 TP_AC20_P = T_POINT_R_0: Assy: DNI; COMPFIXED: NO; COMPGROUP: 0; COMPHEIGHT: 0.000; COMPKEY: NO; COMPLOC: [300.000,3300.000]; COMPLOCKED: NO; COMPROT: 0; COMPSIDE: TOP; DECOUPLER: NO; MEMORY: NO
TP_AB20_N TP_AD3_P = T_POINT_R_0: Assy: DNI; COMPFIXED: NO; COMPGROUP: 0; COMPHEIGHT: 0.000; COMPKEY: NO; COMPLOC: [300.000,3200.000]; COMPLOCKED: NO; COMPROT: 0; COMPSIDE: TOP; DECOUPLER: NO; MEMORY: NO
TP_H1 TP_P23 TP_R26 TP_U3 = T_POINT_R_0: Assy: DNI; COMPFIXED: NO; COMPGROUP: 0; COMPHEIGHT: 0.000; COMPKEY: NO; COMPLOC: [500.000,3000.000]; COMPLOCKED: NO; COMPROT: 0; COMPSIDE: TOP; DECOUPLER: NO; MEMORY: NO
TP_H2 TP_P24 TP_R25 TP_U2 = T_POINT_R_0: Assy: DNI; COMPFIXED: NO; COMPGROUP: 0; COMPHEIGHT: 0.000; COMPKEY: NO; COMPLOC: [500.000,3100.000]; COMPLOCKED: NO; COMPROT: 0; COMPSIDE: TOP; DECOUPLER: NO; MEMORY: NO
TP_P21 TP_T25 = T_POINT_R_0: Assy: DNI; COMPFIXED: NO; COMPGROUP: 0; COMPHEIGHT: 0.000; COMPKEY: NO; COMPLOC: [500.000,3200.000]; COMPLOCKED: NO; COMPROT: 0; COMPSIDE: TOP; DECOUPLER: NO; MEMORY: NO
TP_P22 TP_T26 = T_POINT_R_0: Assy: DNI; COMPFIXED: NO; COMPGROUP: 0; COMPHEIGHT: 0.000; COMPKEY: NO; COMPLOC: [500.000,3300.000]; COMPLOCKED: NO; COMPROT: 0; COMPSIDE: TOP; DECOUPLER: NO; MEMORY: NO
TP_P25 TP_P26 TP_R22 TP_T1-TP_T3 TP_U1 TP_U6 TP_U7 = T_POINT_R_0: Assy: DNI; COMPFIXED: NO; COMPGROUP: 0; COMPHEIGHT: 0.000; COMPKEY: NO; COMPLOC: [500.000,2900.000]; COMPLOCKED: NO; COMPROT: 0; COMPSIDE: TOP; DECOUPLER: NO; MEMORY: NO
TP_R18 TP_T20 = T_POINT_R_0: Assy: DNI; COMPFIXED: NO; COMPGROUP: 0; COMPHEIGHT: 0.000; COMPKEY: NO; COMPLOC: [500.000,3600.000]; COMPLOCKED: NO; COMPROT: 0; COMPSIDE: TOP; DECOUPLER: NO; MEMORY: NO
TP_R19 TP_T21 = T_POINT_R_0: Assy: DNI; COMPFIXED: NO; COMPGROUP: 0; COMPHEIGHT: 0.000; COMPKEY: NO; COMPLOC: [500.000,3700.000]; COMPLOCKED: NO; COMPROT: 0; COMPSIDE: TOP; DECOUPLER: NO; MEMORY: NO
TP_R20 TP_T24 = T_POINT_R_0: Assy: DNI; COMPFIXED: NO; COMPGROUP: 0; COMPHEIGHT: 0.000; COMPKEY: NO; COMPLOC: [500.000,3500.000]; COMPLOCKED: NO; COMPROT: 0; COMPSIDE: TOP; DECOUPLER: NO; MEMORY: NO
TP_R21 TP_T23 = T_POINT_R_0: Assy: DNI; COMPFIXED: NO; COMPGROUP: 0; COMPHEIGHT: 0.000; COMPKEY: NO; COMPLOC: [500.000,3400.000]; COMPLOCKED: NO; COMPROT: 0; COMPSIDE: TOP; DECOUPLER: NO; MEMORY: NO
TP_T19 = T_POINT_R_0: Assy: DNI; COMPFIXED: NO; COMPGROUP: 0; COMPHEIGHT: 0.000; COMPKEY: NO; COMPLOC: [600.000,2900.000]; COMPLOCKED: NO; COMPROT: 0; COMPSIDE: TOP; DECOUPLER: NO; MEMORY: NO
TP_U18 = T_POINT_R_0: Assy: DNI; COMPFIXED: NO; COMPGROUP: 0; COMPHEIGHT: 0.000; COMPKEY: NO; COMPLOC: [600.000,3000.000]; COMPLOCKED: NO; COMPROT: 0; COMPSIDE: TOP; DECOUPLER: NO; MEMORY: NO
TP_U19 = T_POINT_R_0: Assy: DNI; COMPFIXED: NO; COMPGROUP: 0; COMPHEIGHT: 0.000; COMPKEY: NO; COMPLOC: [600.000,3100.000]; COMPLOCKED: NO; COMPROT: 0; COMPSIDE: TOP; DECOUPLER: NO; MEMORY: NO
TP_U22 = T_POINT_R_0: Assy: DNI; COMPFIXED: NO; COMPGROUP: 0; COMPHEIGHT: 0.000; COMPKEY: NO; COMPLOC: [600.000,3300.000]; COMPLOCKED: NO; COMPROT: 0; COMPSIDE: TOP; DECOUPLER: NO; MEMORY: NO
TP_U23 = T_POINT_R_0: Assy: DNI; COMPFIXED: NO; COMPGROUP: 0; COMPHEIGHT: 0.000; COMPKEY: NO; COMPLOC: [600.000,3200.000]; COMPLOCKED: NO; COMPROT: 0; COMPSIDE: TOP; DECOUPLER: NO; MEMORY: NO
TP_U24 = T_POINT_R_0: Assy: DNI; COMPFIXED: NO; COMPGROUP: 0; COMPHEIGHT: 0.000; COMPKEY: NO; COMPLOC: [600.000,3500.000]; COMPLOCKED: NO; COMPROT: 0; COMPSIDE: TOP; DECOUPLER: NO; MEMORY: NO
TP_U25 = T_POINT_R_0: Assy: DNI; COMPFIXED: NO; COMPGROUP: 0; COMPHEIGHT: 0.000; COMPKEY: NO; COMPLOC: [600.000,3400.000]; COMPLOCKED: NO; COMPROT: 0; COMPSIDE: TOP; DECOUPLER: NO; MEMORY: NO
TP_V18 = T_POINT_R_0: Assy: DNI; COMPFIXED: NO; COMPGROUP: 0; COMPHEIGHT: 0.000; COMPKEY: NO; COMPLOC: [600.000,3700.000]; COMPLOCKED: NO; COMPROT: 0; COMPSIDE: TOP; DECOUPLER: NO; MEMORY: NO
TP_V19 = T_POINT_R_0: Assy: DNI; COMPFIXED: NO; COMPGROUP: 0; COMPHEIGHT: 0.000; COMPKEY: NO; COMPLOC: [600.000,3600.000]; COMPLOCKED: NO; COMPROT: 0; COMPSIDE: TOP; DECOUPLER: NO; MEMORY: NO
TP_V20 = T_POINT_R_0: Assy: DNI; COMPFIXED: NO; COMPGROUP: 0; COMPHEIGHT: 0.000; COMPKEY: NO; COMPLOC: [700.000,3400.000]; COMPLOCKED: NO; COMPROT: 0; COMPSIDE: TOP; DECOUPLER: NO; MEMORY: NO
TP_V22_N TP_W12_N TP_Y12_P = T_POINT_R_0: Assy: DNI; COMPFIXED: NO; COMPGROUP: 0; COMPHEIGHT: 0.000; COMPKEY: NO; COMPLOC: [300.000,2900.000]; COMPLOCKED: NO; COMPROT: 0; COMPSIDE: TOP; DECOUPLER: NO; MEMORY: NO
125MHZ = T_POINT_R: Assy: DNI
C64 = 10uF_0603
C69 = 0u1_0402: CAP CER 0.1UF 16V 10% X7R 0402
JP11-JP13 JP15 JP16 = JUMPER_0
JP14 = Receptacle_20X2
R55 = R: RES SMD 33 OHM 1% 1/10W 0402; Manufacturer: Panasonic; Manufacturer Part Number: ERJ-2RKF33R0X
R103-R108 R263-R266 = 0R_0603: RES 0.0 OHM 1/10W JUMP 0603 SMD; Assy: DNI
R109 = RESISTOR: RES 10K OHM 1/10W 5% 0603
R110 = 1R_0.25W_0603: Manufacturer: Vishay
U3 = LFCPNX100K-FFG672
X3 = ASDMB: MEMS OSC XO 125.0000MHZ LVCMOS; Manufacturer: Abracon LLC
C138-C140 C163 C168 C169 C181 = CAP_NP: COMPFIXED: NO; COMPGROUP: 0; COMPHEIGHT: 0.000; COMPKEY: NO; COMPLOC: [1820.000,2015.000]; COMPLOCKED: NO; COMPROT: 270; COMPSIDE: TOP; DECOUPLER: NO; FPLIST: SM/C_0402; MEMORY: NO
C142-C158 C160 C164-C167 C171-C174 C176-C179 C182 C183 = CAP_1: CAP CER 0.1UF 25V 10% X5R 0201; Manufacturer: Murata; Manufacturer Part Number: GRM033R61E104KE14J
C159 C161 C162 C175 C180 = CAP_SMT_0805: CAP CER 0.1UF 25V 10% X5R 0201; Manufacturer: Murata; Manufacturer Part Number: GRM033R61E104KE14J
FB7-FB12 FB14 = INDUCTOR_1: FERRITE BEAD 120 OHM 0402 1LN; Manufacturer: TDK Corporation; Manufacturer Part Number: MPZ1005S121CT000
FB15-FB17 = INDUCTOR_0: FERRITE BEAD 120 OHM 0402 1LN; Manufacturer: TDK Corporation
27G_SMA1 27G_SMA2 27G_SMA5 27G_SMA6 27G_SMA9 27G_SMA10 27G_SMA13 27G_SMA14 = CONNECTOR_COAX-test_1: CONN SMA JACK STR 50 OHM SMD; MFG: Amphenol SV Microwave; Manufacturer: Amphenol SV Microwave; Pckg: 3 PIN THRU BD-Via StripLine; VENDOR: Digikey; Vendor P/N: SF2921-61356-2S-ND
27G_SMA3 27G_SMA4 27G_SMA7 27G_SMA8 27G_SMA11 27G_SMA12 27G_SMA15 27G_SMA16 = CONNECTOR_COAX-test_1: CONN SMA JACK STR 50 OHM SMD; MFG: Amphenol SV Microwave; MFG P/N: SF2921-61345-2S; Manufacturer: Amphenol SV Microwave; Manufacturer Part Number: SF2921-61345-2S; Pckg: 3 PIN THRU BD-Via StripLine; VENDOR: Digikey; Vendor P/N: SF2921-61345-2S-ND
C59 C60 C248 C249 C271-C286 = C: Populate: DI
C89 C91 C93 C95 C97 C99 C101 C103 C105 C107 C109 C111 C113 C115 C117 C119 = CAP-NP: CAP CER 0.47UF 10V X7S 0402; MAX_TEMP: 125; MFG: TDK Corporation; MFG P/N: CGA2B3X7S1A474K050BE; Manufacturer: TDK Corporation; Manufacturer Part Number: CGA2B3X7S1A474K050BE; VENDOR: Digikey; VENDOR P/N: 445-173723-1-ND
C90 C92 C94 C96 C98 C100 C102 C104 C106 C108 C110 C112 C114 C116 C118 C120 = CAP-NP: CAP CER 47UF 6.3V X5R 0603; MAX_TEMP: 85; MFG: Murata Electronics; MFG P/N: GRM188R60J476ME15D; Manufacturer: Murata Electronics; Manufacturer Part Number: GRM188R60J476ME15D; VENDOR: Digikey; VENDOR P/N: 490-13247-6-ND
R102 R236 = R
R117-R124 = RESISTOR: Populate: <Populate>
R213 R214 R222-R226 R229-R231 R234 R235 R260 R261 = R_v3: RES SMD 0.0OHM JUMPER 1/10W 0402; COMPFIXED: NO; COMPGROUP: 0; COMPHEIGHT: 0.000; COMPKEY: NO; COMPLOC: [3325.000,1400.000]; COMPLOCKED: NO; COMPROT: 180; COMPSIDE: TOP; DECOUPLER: NO; FPLIST: AX/RC05; MEMORY: NO; Manufacturer: Panasonic; Manufacturer Part Number: ERJ-2GE0R00X
R218-R221 R227 R228 R232 R233 = R_v3: RES SMD 0.0OHM JUMPER 1/10W 0402; COMPFIXED: NO; COMPHEIGHT: 0.000; COMPKEY: NO; COMPLOC: [3325.000,1400.000]; COMPLOCKED: NO; COMPROT: 180; COMPSIDE: TOP; DECOUPLER: NO; FPLIST: AX/RC05; MEMORY: NO; Manufacturer: Panasonic; Manufacturer Part Number: ERJ-2GE0R00X
SMA1 SMA2 = CONNECTOR_COAX-M_0: CONN SMA JACK STR 50 OHM PCB; COMMENT: Fig4_SMA; MFG: Samtec Inc.; MFG P/N: SMA-J-P-H-ST-TH1; PCB Mounting: Molex Doc # SD-73391-007; Pckg: 5 PIN THRU; VENDOR: Digikey; Vendor P/N: SAM8971-ND
U27 = NX33G1101Z
X2 = XO-400_1: MEMS OSC XO 100.0000MHZ LVDS SMD; Manufacturer: Abracon LLC; Manufacturer Part Number: ASTMUPLDE-100.000MHZ-LJ-E-T

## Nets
GND: 27G_SMA1.2(SHIELD2) 27G_SMA1.G1 27G_SMA1.G2 27G_SMA2.2(SHIELD2) 27G_SMA2.G1 27G_SMA2.G2 27G_SMA3.2(SHIELD2) 27G_SMA3.G1 27G_SMA3.G2 27G_SMA4.2(SHIELD2) 27G_SMA4.G1 27G_SMA4.G2 27G_SMA5.2(SHIELD2) 27G_SMA5.G1 27G_SMA5.G2 27G_SMA6.2(SHIELD2) 27G_SMA6.G1 27G_SMA6.G2 27G_SMA7.2(SHIELD2) 27G_SMA7.G1 27G_SMA7.G2 27G_SMA8.2(SHIELD2) 27G_SMA8.G1 27G_SMA8.G2 27G_SMA9.2(SHIELD2) 27G_SMA9.G1 27G_SMA9.G2 27G_SMA10.2(SHIELD2) 27G_SMA10.G1 27G_SMA10.G2 27G_SMA11.2(SHIELD2) 27G_SMA11.G1 27G_SMA11.G2 27G_SMA12.2(SHIELD2) 27G_SMA12.G1 27G_SMA12.G2 27G_SMA13.2(SHIELD2) 27G_SMA13.G1 27G_SMA13.G2 27G_SMA14.2(SHIELD2) 27G_SMA14.G1 27G_SMA14.G2 27G_SMA15.2(SHIELD2) 27G_SMA15.G1 27G_SMA15.G2 27G_SMA16.2(SHIELD2) 27G_SMA16.G1 27G_SMA16.G2 C59.1 C60.1 C61.2 C62.2 C63.2 C64.2 C65.2 C66.2 C67.2 C68.2 C69.2 C70.1 C71.1 C72.1 C73.1 C74.1 C75.1 C76.1 C77.1 C78.1 C79.1 C80.1 C81.1 C82.1 C83.1 C84.1 C85.1 C86.1 C87.1 C88.1 C121.2 C122.2 C123.2 C124.1 C125.1 C130.2 C131.2 C132.2 C133.2 C134.2 C135.2 C136.2 C137.2 C138.1 C139.1 C140.1 C141.2 C142.2 C143.2 C144.2 C145.2 C146.2 C147.2 C148.2 C149.2 C150.2 C151.2 C152.2 C153.2 C154.2 C155.2 C156.2 C157.2 C158.2 C159.2 C160.2 C161.2 C162.2 C163.1 C164.2 C165.2 C166.2 C167.2 C168.1 C169.1 C170.2 C171.2 C172.2 C173.2 C174.2 C175.2 C176.2 C177.2 C178.2 C179.2 C180.2 C181.1 C182.2 C183.2 C248.1 C249.1 GND1.1(TP) GND2.1(TP) GND3.1(TP) GND4.1(TP) GND5.1(TP) GND6.1(TP) GND7.1(TP) GND8.1(TP) GND9.1(TP) GND10.1(TP) GND11.1(TP) GND12.1(TP) GND13.1(TP) GND14.1(TP) GND15.1(TP) GND16.1(TP) GND17.1(TP) GND18.1(TP) GND19.1(TP) GND20.1(TP) GND21.1(TP) GND22.1(TP) GND23.1(TP) GND24.1(TP) GND25.1(TP) GND26.1(TP) J21.1 J22.1 J22.2 J22.4 J22.6 J22.7 J22.8 J22.10 J22.12 J22.13 J22.14 J22.16 J22.17 J22.18 J22.20 J31.1 J32.1 J33.1 JP11.2 JP14.6 JP14.9 JP14.14 JP14.20 JP14.25 JP14.30 JP14.34 JP14.39 JP15.1 JP16.2 R125.2 R222.2 R223.1 R224.2 R225.1 R229.2 R230.1 R234.2 R235.1 SMA1.2(SHIELD2) SMA1.3(SHIELD1) SMA1.4(SHIELD4) SMA1.5(SHIELD3) SMA2.2(SHIELD2) SMA2.3(SHIELD1) SMA2.4(SHIELD4) SMA2.5(SHIELD3) U3.AD2(VSSADC) U7.2(GND) U8.1 U27.3(GND) X2.3(GND) X3.2(GND) ; also on sheet 3 4 5 6 7 8 15 16
V1P8_ADC_VREF: C122.1 J17.1 J18.1 R125.1 U7.5(OUTS) U7.6(OUTF)
VCC_1V2: 1V2.1(TP) R135.2 R146.2 ; also on sheet 15
VCC_1V8: 1V8.1(TP) R132.2 R133.2 R141.2 R144.2 R150.2 ; also on sheet 15
VCC_1V_CORE: FB14.2 FB15.1 ; also on sheet 15
VCC_2V5: 2V5.1(TP) R138.2 R148.2 ; also on sheet 15
VCC_3V3: C134.1 C137.1 FB5.2 FB6.1 FB19.2 J27.2 J30.2 JP12.1 L2.2 R109.2 R134.2 R136.2 R143.1 R145.2 R151.2 ; also on sheet 3 4 5 8 15
VCC_5V: 5V.1(TP) JP13.1 ; also on sheet 15
VCC_ADJ: ADJ.1(TP) R259.2 R262.2 ; also on sheet 8
VCCA_1V: FB7.2 FB8.2 ; also on sheet 15
VCCA_1V8: FB9.2 FB10.2 FB11.2 FB12.2 FB13.2 FB16.1 FB17.1 U8.3 ; also on sheet 15
VCCADC18: C124.2 C125.2 J19.2 R126.2 U3.AC3(VCCADC18)
VCCAUXSD0: C93.2 C94.1 C101.2 C102.1 C109.2 C110.1 C117.2 C118.1 J13.2 R113.2 U3.J16(VCCAUXSDQ0) V1P8_VCCAUXSDQ0.1(TP)
VCCAUXSD1: C95.2 C96.1 C103.2 C104.1 C111.2 C112.1 C119.2 C120.1 J14.2 R114.2 U3.J13(VCCAUXSDQ1) V1P8_VCCAUXSDQ1.1(TP)
VCCIO0: J23.1 R139.1 VCCIO0.1(TP) ; also on sheet 4
VCCIO0_IN: C130.1 J23.2 R133.1 R136.1 R139.2 ; also on sheet 4
VCCIO1: J27.1 R143.2 VCCIO1.1(TP) ; also on sheet 5
VCCIO2: J25.1 R140.1 VCCIO2.1(TP) ; also on sheet 6
VCCIO2_IN: C132.1 J25.2 R134.1 R138.1 R140.2 R141.1 ; also on sheet 6
VCCIO3: J24.1 R137.1 VCCIO3.1(TP) ; also on sheet 7
VCCIO4: J26.1 R142.1 VCCIO4.1(TP) ; also on sheet 7
VCCIO5: J28.1 R147.1 VCCIO5.1(TP) ; also on sheet 7
VCCIO6: C61.1 C62.1 C63.1 J29.1 R149.1 U3.R23(VCCIO6) U3.U20(VCCIO6) VCCIO6.1(TP)
VCCIO7: C64.1 C65.1 C66.1 J30.1 R151.1 U3.K22(VCCIO7) U3.M20(VCCIO7) VCCIO7.1(TP)
VCCPLLSD0: C89.2 C90.1 C97.2 C98.1 C105.2 C106.1 C113.2 C114.1 J15.2 R115.2 U3.E18(VCCPLLSD3) U3.F19(VCCPLLSD2) U3.F22(VCCPLLSD0) U3.G22(VCCPLLSD1) V1P8_VCCPLLSD0.1(TP)
VCCPLLSD1: C91.2 C92.1 C99.2 C100.1 C107.2 C108.1 C115.2 C116.1 J16.2 R116.2 U3.E16(VCCPLLSD4) U3.F12(VCCPLLSD7) U3.F15(VCCPLLSD6) U3.H15(VCCPLLSD5) V1P8_VCCPLLSD1.1(TP)
VDD_3V3: 3V3.1(TP) ; also on sheet 8
125_MHz: 125MHZ.1(TP) R110.2 U3.N25(PL29A/PCLKT7_1)
CLOCK_100MHZ_N: R221.1 X2.5(Q_N)
CLOCK_100MHZ_P: R220.1 X2.4(Q)
CLOCK_161MHZ_N: R228.1 U27.5(~{Q})
CLOCK_161MHZ_P: R227.1 U27.4(Q)
EPS0_V20_P: TP_V20.1(TP) U3.V20(PL67A)
EPS0_V21_N: TP_V21.1(TP) U3.V21(PL67B)
EPS1_V18_P: TP_V18.1(TP) U3.V18(PL65A)
EPS1_V19_N: TP_V19.1(TP) U3.V19(PL65B)
EPS2_U24_P: TP_U24.1(TP) U3.U24(PL64A)
EPS2_U25_N: TP_U25.1(TP) U3.U25(PL64B)
EPS3_U22_P: TP_U22.1(TP) U3.U22(PL62A)
EPS3_U23_N: TP_U23.1(TP) U3.U23(PL62B)
EPS4_U18_N: TP_U18.1(TP) U3.U18(PL60B)
EPS4_U19_P: TP_U19.1(TP) U3.U19(PL60A)
EPS5_T18_N: TP_T18.1(TP) U3.T18(PL58B)
EPS5_T19_P: TP_T19.1(TP) U3.T19(PL58A)
EPS6_T20_N: TP_T20.1(TP) U3.T20(PL56B)
EPS6_T21_P: TP_T21.1(TP) U3.T21(PL56A)
EPS7_T23_N: TP_T23.1(TP) U3.T23(PL55B)
EPS7_T24_P: TP_T24.1(TP) U3.T24(PL55A)
EPS8_T25_N: TP_T25.1(TP) U3.T25(PL53B)
EPS8_T26_P: TP_T26.1(TP) U3.T26(PL53A)
EPS9_R25_P: TP_R25.1(TP) U3.R25(PL51A)
EPS9_R26_N: TP_R26.1(TP) U3.R26(PL51B)
EPS10_R22_P: TP_R22.1(TP) U3.R22(PL49A)
EPS10_T22_N: TP_T22.1(TP) U3.T22(PL49B)
EPS11_R18_N: TP_R18.1(TP) U3.R18(PL47B)
EPS11_R19_P: TP_R19.1(TP) U3.R19(PL47A)
EPS12_R20_P: TP_R20.1(TP) U3.R20(PL46A/PCLKT6_2)
EPS12_R21_N: TP_R21.1(TP) U3.R21(PL46B)
EPS13_P21_N: TP_P21.1(TP) U3.P21(PL44B)
EPS13_P22_P: TP_P22.1(TP) U3.P22(PL44A/PCLKT6_1)
EPS14_P23_N: TP_P23.1(TP) U3.P23(PL42B)
EPS14_P24_P: TP_P24.1(TP) U3.P24(PL42A/PCLKT6_0)
EPS15_P25_N: TP_P25.1(TP) U3.P25(PL40B)
EPS15_P26_P: TP_P26.1(TP) U3.P26(PL40A)
EPS16_H1_N: TP_H1.1(TP) ; also on sheet 4
EPS16_H2_P: TP_H2.1(TP) ; also on sheet 4
EPS17_J1: TP_J1.1(TP) ; also on sheet 4
EPS17_T2_N: TP_T2.1(TP) ; also on sheet 6
EPS17_T3_P: TP_T3.1(TP) ; also on sheet 6
EPS18_T1_P: TP_T1.1(TP) ; also on sheet 6
EPS18_U1_N: TP_U1.1(TP) ; also on sheet 6
EPS19_U2_P: TP_U2.1(TP) ; also on sheet 6
EPS19_U3_N: TP_U3.1(TP) ; also on sheet 6
EPS20_U6_P: TP_U6.1(TP) ; also on sheet 6
EPS20_U7_N: TP_U7.1(TP) ; also on sheet 6
EPS21_AD3_P: TP_AD3_P.1(TP) ; also on sheet 7
EPS21_AE3_N: TP_AE3_N.1(TP) ; also on sheet 7
EPS22_W12_N: TP_W12_N.1(TP) ; also on sheet 7
EPS22_Y12_P: TP_Y12_P.1(TP) ; also on sheet 7
EPS23_AB20_N: TP_AB20_N.1(TP) ; also on sheet 7
EPS23_AC20_P: TP_AC20_P.1(TP) ; also on sheet 7
EPS24_V22_N: TP_V22_N.1(TP) ; also on sheet 7
EPS24_V23_P: TP_V23_P.1(TP) ; also on sheet 7
FMC_GBTCLK0_M2C_N: R233.1 ; also on sheet 8
FMC_GBTCLK0_M2C_P: R232.1 ; also on sheet 8
FMC_GBTCLK1_M2C_N: R219.1 ; also on sheet 8
FMC_GBTCLK1_M2C_P: R218.1 ; also on sheet 8
FMC_PG_C2M: U3.J22(PL10B) ; also on sheet 8
FMC_PG_M2C: U3.J25(PL8A) ; also on sheet 8
FMC_PRSNT_M2C_L: U3.H21(PL3B/ULC_GPLL0C_IN) ; also on sheet 8
FMC_SCL: U3.H22(PL4A/ULC_GPLL0T_MFGOUT1) ; also on sheet 8
FMC_SD0_RXD_N: U3.G25(SD0_RXDN) ; also on sheet 8
FMC_SD0_RXD_P: U3.G24(SD0_RXDP) ; also on sheet 8
FMC_SD0_TXD_N: U3.E26(SD0_TXDN) ; also on sheet 8
FMC_SD0_TXD_P: U3.F26(SD0_TXDP) ; also on sheet 8
FMC_SD1_RXD_N: U3.D25(SD1_RXDN) ; also on sheet 8
FMC_SD1_RXD_P: U3.E24(SD1_RXDP) ; also on sheet 8
FMC_SD1_TXD_N: U3.B26(SD1_TXDN) ; also on sheet 8
FMC_SD1_TXD_P: U3.C26(SD1_TXDP) ; also on sheet 8
FMC_SD2_RXD_N: U3.B23(SD2_RXDN) ; also on sheet 8
FMC_SD2_RXD_P: U3.C24(SD2_RXDP) ; also on sheet 8
FMC_SD2_TXD_N: U3.A24(SD2_TXDN) ; also on sheet 8
FMC_SD2_TXD_P: U3.A25(SD2_TXDP) ; also on sheet 8
FMC_SD3_RXD_N: U3.C22(SD3_RXDN) ; also on sheet 8
FMC_SD3_RXD_P: U3.C21(SD3_RXDP) ; also on sheet 8
FMC_SD3_TXD_N: U3.A21(SD3_TXDN) ; also on sheet 8
FMC_SD3_TXD_P: U3.A22(SD3_TXDP) ; also on sheet 8
FMC_SDA: U3.H23(PL4B/ULC_GPLL0T_MFGOUT2) ; also on sheet 8
FMC_TCK: R55.1 ; also on sheet 8
FMC_TDI: U3.J24(PL8B) ; also on sheet 8
FMC_TDO: U3.H26(PL6A) ; also on sheet 8
FMC_TMS: U3.J26(PL6B) ; also on sheet 8
LVCMOS_CLK_DIS: JP15.2 R109.1 U3.J23(PL10A) X3.1(Standby)
LVDS_100CLK_DIS: JP11.1 R102.1 U3.N24(PL29B) X2.1(EN)
LVDS_161CLK_DIS: JP16.1 R236.1 U27.1(OE) ; also on sheet 5
R_ext_0: R117.1 U3.E21(SD0_REXT)
R_ext_1: R119.1 U3.G20(SD1_REXT)
R_ext_2: R121.1 U3.D19(SD2_REXT)
R_ext_3: R123.1 U3.C18(SD3_REXT)
R_ext_4: R118.1 U3.D17(SD4_REXT)
R_ext_5: R120.1 U3.K15(SD5_REXT)
R_ext_6: R122.1 U3.D15(SD6_REXT)
R_ext_7: R124.1 U3.E13(SD7_REXT)
RASP_5V: C68.1 JP13.2 JP14.2 JP14.4
RASP_ID_SC: JP14.28 R103.1 U3.P19(PL38A)
RASP_ID_SD: JP14.27 R104.1 U3.P20(PL38B)
RASP_IO02: JP14.3 U3.K26(PL20A)
RASP_IO03: JP14.5 U3.L26(PL20B)
RASP_IO04: JP14.7 U3.K25(PL19B)
RASP_IO05: JP14.29 R108.2 U3.L20(PL26A)
RASP_IO06: JP14.31 R105.2 U3.L19(PL26B)
RASP_IO07: JP14.26 U3.K18(PL15A)
RASP_IO08: JP14.24 U3.K19(PL15B)
RASP_IO09: JP14.21 U3.K20(PL13B)
RASP_IO10: JP14.19 U3.J19(PL13A)
RASP_IO11: JP14.23 R106.2 U3.M26(PL28A/PCLKT7_2)
RASP_IO12: JP14.32 U3.L21(PL17B)
RASP_IO13: JP14.33 U3.N23(PL31A/PCLKT7_0)
RASP_IO14: JP14.8 U3.L25(PL22A)
RASP_IO15: JP14.10 U3.K24(PL19A)
RASP_IO16: JP14.36 U3.N19(PL35A)
RASP_IO17: JP14.11 U3.L24(PL22B)
RASP_IO18: JP14.12 R107.2 U3.N26(PL28B)
RASP_IO19: JP14.35 U3.N22(PL31B)
RASP_IO20: JP14.38 U3.N21(PL33A)
RASP_IO21: JP14.40 U3.P18(PL35B)
RASP_IO22: JP14.15 U3.L23(PL24A)
RASP_IO23: JP14.16 U3.J20(PL11B)
RASP_IO24: JP14.18 U3.K21(PL17A)
RASP_IO25: JP14.22 U3.L22(PL24B)
RASP_IO26: JP14.37 U3.N20(PL33B)
RASP_IO27: JP14.13 U3.J21(PL11A)
Ref_return_pll_0: C89.1 C90.2 C93.1 C94.2 R117.2 U3.E22(SD0_REFRET)
Ref_return_pll_1: C97.1 C98.2 C101.1 C102.2 R119.2 U3.G21(SD1_REFRET)
Ref_return_pll_2: C105.1 C106.2 C109.1 C110.2 R121.2 U3.E19(SD2_REFRET)
Ref_return_pll_3: C113.1 C114.2 C117.1 C118.2 R123.2 U3.D18(SD3_REFRET)
Ref_return_pll_4: C91.1 C92.2 C95.1 C96.2 R118.2 U3.E17(SD4_REFRET)
Ref_return_pll_5: C99.1 C100.2 C103.1 C104.2 R120.2 U3.J15(SD5_REFRET)
Ref_return_pll_6: C107.1 C108.2 C111.1 C112.2 R122.2 U3.E15(SD6_REFRET)
Ref_return_pll_7: C115.1 C116.2 C119.1 C120.2 R124.2 U3.E12(SD7_REFRET)
SCL: R103.2 ; also on sheet 3 5
SD_EXT0_REFCLK_N: R231.1 R233.2 R235.2 R260.2 U3.E11(SD_EXT0_REFCLKN)
SD_EXT0_REFCLK_P: R231.2 R232.2 R234.1 R261.1 U3.D11(SD_EXT0_REFCLKP)
SD_EXT1_REFCLK_N: R214.1 R219.2 R225.2 U3.D9(SD_EXT1_REFCLKN)
SD_EXT1_REFCLK_P: R214.2 R218.2 R224.1 U3.E10(SD_EXT1_REFCLKP)
SDA: R104.2 ; also on sheet 3 5
SDQ0_REFCLK_N: R213.1 R221.2 R223.2 U3.E20(SDQ0_REFCLKN)
SDQ0_REFCLK_P: R213.2 R220.2 R222.1 U3.F20(SDQ0_REFCLKP)
SDQ1_REFCLK_N: R226.1 R228.2 R230.2 U3.D13(SDQ1_REFCLKN)
SDQ1_REFCLK_P: R226.2 R227.2 R229.1 U3.C14(SDQ1_REFCLKP)
SMA_SD4_RXD_C_N: C272.2 U3.B19(SD4_RXDN)
SMA_SD4_RXD_C_P: C271.2 U3.B20(SD4_RXDP)
SMA_SD4_RXD_N: 27G_SMA2.1(CENTER) C272.1
SMA_SD4_RXD_P: 27G_SMA1.1(CENTER) C271.1
SMA_SD4_TXD_C_N: C274.2 U3.A17(SD4_TXDN)
SMA_SD4_TXD_C_P: C273.2 U3.A18(SD4_TXDP)
SMA_SD4_TXD_N: 27G_SMA4.1(CENTER) C274.1
SMA_SD4_TXD_P: 27G_SMA3.1(CENTER) C273.1
SMA_SD5_RXD_C_N: C276.2 U3.B16(SD5_RXDN)
SMA_SD5_RXD_C_P: C275.2 U3.C16(SD5_RXDP)
SMA_SD5_RXD_N: 27G_SMA6.1(CENTER) C276.1
SMA_SD5_RXD_P: 27G_SMA5.1(CENTER) C275.1
SMA_SD5_TXD_C_N: C278.2 U3.A14(SD5_TXDN)
SMA_SD5_TXD_C_P: C277.2 U3.A15(SD5_TXDP)
SMA_SD5_TXD_N: 27G_SMA8.1(CENTER) C278.1
SMA_SD5_TXD_P: 27G_SMA7.1(CENTER) C277.1
SMA_SD6_RXD_C_N: C280.2 U3.C12(SD6_RXDN)
SMA_SD6_RXD_C_P: C279.2 U3.B13(SD6_RXDP)
SMA_SD6_RXD_N: 27G_SMA10.1(CENTER) C280.1
SMA_SD6_RXD_P: 27G_SMA9.1(CENTER) C279.1
SMA_SD6_TXD_C_N: C282.2 U3.A11(SD6_TXDN)
SMA_SD6_TXD_C_P: C281.2 U3.A12(SD6_TXDP)
SMA_SD6_TXD_N: 27G_SMA12.1(CENTER) C282.1
SMA_SD6_TXD_P: 27G_SMA11.1(CENTER) C281.1
SMA_SD7_RXD_C_N: C284.2 U3.C10(SD7_RXDN)
SMA_SD7_RXD_C_P: C283.2 U3.B10(SD7_RXDP)
SMA_SD7_RXD_N: 27G_SMA14.1(CENTER) C284.1
SMA_SD7_RXD_P: 27G_SMA13.1(CENTER) C283.1
SMA_SD7_TXD_C_N: C286.2 U3.A8(SD7_TXDN)
SMA_SD7_TXD_C_P: C285.2 U3.A9(SD7_TXDP)
SMA_SD7_TXD_N: 27G_SMA16.1(CENTER) C286.1
SMA_SD7_TXD_P: 27G_SMA15.1(CENTER) C285.1
TCK: R264.1 ; also on sheet 3 5
TCK_R: R106.1 R264.2
TDI: R266.1 ; also on sheet 3 5
TDI_R: R105.1 R266.2
TDO: R265.1 ; also on sheet 3 5
TDO_R: R108.1 R265.2
TMS: R263.1 ; also on sheet 3 5
TMS_R: R107.1 R263.2
VREF1_CON: J17.3 J22.19
VREF2_CON: J18.3 J22.15
N17096289: C138.2 C139.2 C140.2 C141.1 C142.1 C143.1 C144.1 C145.1 C146.1 C147.1 C148.1 C149.1 C150.1 C151.1 C152.1 C153.1 C154.1 C155.1 C156.1 C157.1 C158.1 C159.1 C160.1 C161.1 C162.1 J34.2 R152.2 U3.L10(VCC) U3.L15(VCC) U3.M12(VCC) U3.M14(VCC) U3.N11(VCC) U3.N13(VCC) U3.N15(VCC) U3.N17(VCC) U3.P10(VCC) U3.P12(VCC) U3.P14(VCC) U3.P16(VCC) U3.R11(VCC) U3.R13(VCC) U3.R15(VCC) U3.T10(VCC) U3.T12(VCC) U3.T14(VCC) U3.T16(VCC) U3.U11(VCC) U3.U13(VCC) VCC_CORE.1(TP)
N18929092: C131.1 C133.1 C135.1 J24.2 J26.2 J28.2 R132.1 R135.1 R137.2 R142.2 R144.1 R146.1 R147.2 R259.1 R262.1
N18930316: C136.1 J29.2 R145.1 R148.1 R149.2 R150.1
N19421129: FB14.1 J34.1 R152.1
N19766059: C163.2 C164.1 C165.1 C166.1 C167.1 J35.2 R153.2 U3.T9(VCCECLK) U3.V12(VCCECLK) U3.V14(VCCECLK) U3.V16(VCCECLK) VCCECLK.1(TP)
N19766144: C168.2 C169.2 C170.1 C171.1 C172.1 C173.1 C174.1 C175.1 C176.1 C177.1 C178.1 C179.1 C180.1 J36.2 R154.2 U3.L17(VCCAUX) U3.M10(VCCAUX) U3.R17(VCCAUX) U3.U10(VCCAUX) U3.U15(VCCAUXH4) U3.U17(VCCAUXH5) U3.V9(VCCAUXH3) U3.V10(VCCAUXH3) U3.V15(VCCAUXH4) U3.V17(VCCAUXH5) VCCAUX.1(TP)
N19766595: FB16.2 J36.1 R154.1
N19766964: FB15.2 J35.1 R153.1
N19767220: C181.2 C182.1 C183.1 J37.2 R155.2 U3.L12(VCCAUXA) U3.L14(VCCAUXA) VCCAUXA.1(TP)
N19767222: FB17.2 J37.1 R155.1
N19845080: C70.2 C71.2 C72.2 C73.2 C74.2 C75.2 C76.2 C77.2 C78.2 C79.2 C80.2 C81.2 C82.2 C83.2 C84.2 C85.2 C86.2 J11.2 R111.2 U3.F16(VCCSD4) U3.F17(VCCSD4) U3.G13(VCCSD7) U3.G15(VCCSD5) U3.G17(VCCSD3) U3.G18(VCCSD1) U3.G19(VCCSD0) U3.H13(VCCSD7) U3.H16(VCCSD5) U3.H17(VCCSD3) U3.H19(VCCSD0) U3.J14(VCCSD6) U3.J18(VCCSD1) U3.K14(VCCSD6) U3.K16(VCCSD2) U3.K17(VCCSD2) V1P0_VCCSD.1(TP)
N19845094: FB11.1 J15.1 R115.1
N19845320: FB7.1 J11.1 R111.1
N19858461: C87.2 C88.2 J12.2 R112.2 U3.M16(VCCSDCK) V1P0_VCCSDCK.1(TP)
N19858474: FB8.1 J12.1 R112.1
N19859777: FB9.1 J13.1 R113.1
N19904427: C128.2 C129.2 R131.2 U3.AD1(ADC_DN1)
N19904429: J18.2 U3.AC2(ADC_REFP1)
N19904445: J17.2 U3.AC1(ADC_REFP0)
N19904462: C126.2 C127.2 J21.2 U3.AE2(ADC_DN0)
N19904464: C126.1 C127.1 R128.2 U3.AF2(ADC_DP0)
N19904478: J22.11 R131.1
N19904495: C128.1 C129.1 R130.2 U3.AE1(ADC_DP1)
N19904574: J20.3 J22.3
N19904606: C121.1 L2.1 U7.3(EN) U7.4(IN)
N19904637: C123.1 U7.1(FILTER)
N19904671: J20.1 R127.2
N19904703: J21.3 R129.1
N19904717: J20.2 R128.1
N19904734: FB13.1 J19.1 R126.1
N19904873: J22.9 R130.1
N19904898: J22.5 R129.2
N19904948: R127.1 U8.2
N19950169: C67.1 JP12.2 JP14.1 JP14.17
N19950707: C69.1 FB6.2 X3.4(VDD)
N19950727: R110.1 X3.3(OUT)
N19963300: FB10.1 J14.1 R114.1
N19965572: FB12.1 J16.1 R116.1
N20343893: C59.2 C60.2 FB5.1 R102.2 X2.6(VCC)
N20346198: C248.2 C249.2 FB19.1 R236.2 U27.6(VCC)
N20470240: R55.2 U3.H20(PL3A/ULC_GPLL0T_IN)
N20510217: R260.1 SMA2.1(CENTER)
N20510235: R261.2 SMA1.1(CENTER)

Not connected (* = marked no-connect by the designer): U27 2(NC)*; X2 2(NC)*

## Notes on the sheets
sheet 9
- Through Hole Extended Area
- 3.3V/
  2.5V/
  1.8V
- LVCMOS&LVDS Through Hole Extended Area
sheet 10
- Raspberry PI and User I/O Connector
- JP12 & JP13 Power For JP14
  Default Open
- PI_3.3V
- PI_5V
- Reduce stub
- 3.3V
- X3_DIS
- 50 ohm trace
- 2.5 x 2.0 mm 4-SMD
- PLACE X4 CLOSE TO U3
sheet 11
- PLL filter with DCR<=0.1 ohm
  DC must be <<5% drop across
  anti-resonance resistor under
  worst case
- Place PLL series resistor,
  two  caps and r_ext right
  underneath the chip on the
  reverse side of the board
- Place PLL series resistor,
  two  caps and r_ext right
  underneath the chip on the
  reverse side of the board
- X2_DIS
- U27_DIS
- R_ext is chosen for 100 ohm Diff
- R_ext is chosen for 100 ohm Diff
- Place PLL series resistor,
  two  caps and r_ext right
  underneath the chip on the
  reverse side of the board
- Place PLL series resistor,
  two  caps and r_ext right
  underneath the chip on the
  reverse side of the board
- R_ext is chosen for 100 ohm Diff
- R_ext is chosen for 100 ohm Diff
- Stacked pad
- Stacked pad
- Stacked pad
- Stacked pad
- Place PLL series resistor,
  two  caps and r_ext right
  underneath the chip on the
  reverse side of the board
- Place PLL series resistor,
  two  caps and r_ext right
  underneath the chip on the
  reverse side of the board
- R_ext is chosen for 100 ohm Diff
- R_ext is chosen for 100 ohm Diff
- Stacked pad
- Stacked pad
- Place PLL series resistor,
  two  caps and r_ext right
  underneath the chip on the
  reverse side of the board
- Place PLL series resistor,
  two  caps and r_ext right
  underneath the chip on the
  reverse side of the board
- Stacked pad
- Stacked pad
- R_ext is chosen for 100 ohm Diff
- R_ext is chosen for 100 ohm Diff
sheet 12
- J17: 1-2 = V1P8_ADC_VREF (Default)
          2-3 = J22 connector input
- J18: 1-2 = V1P8_ADC_VREF (Default)
          2-3 = J22 connector input
- 1.8v
- 10K POT
- J20 ADC_DP0 Select
  1-2 = POT (Default)
  2-3 = J22 Connector
- J21 ADC_DN0 Select
  1-2 = Ground (Default)
  2-3 = J22 Connector
- Keep noisy signals away from ADC circuit
sheet 13
- R133 installed VCCIO0 =1.8V  (Default)
  R136 installed VCCIO0 =3.3V
  Note:
  R133 or R136 resistors modification align with external Flash power level
- R259&R262 installed VCCIO3&4&5 =FMC adjustable power (Default)
  R132&R144 installed VCCIO3&4&5 =1.8V
  R135&R146 installed VCCIO3&4&5 =1.2V
  Note:
  VCCIO3&4&5 bank power level do NOT exceed 1.8V
- R134 installed VCCIO2 =3.3V  (Default)
  R138 installed VCCIO2 =2.5V
  R141 installed VCCIO2 =1.8V
- VCCIO1 & VCCIO7 =3.3V  ONLY
- R145 installed VCCIO6 =3.3V  (Default)
  R148 installed VCCIO6 =2.5V
  R150 installed VCCIO6 =1.8V
- spread across board, easy access,thermal relief
sheet 14
- VCC_CORE = 1.0 V
